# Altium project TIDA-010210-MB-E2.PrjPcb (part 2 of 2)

## Sheet Voltage Sensing-Pg4.SchDoc
size 431 x 279 mm; Date: Not shown in title block; ApprovedBy: Not shown in title block; CheckedBy: Not shown in title block; Author: Not shown in title block; CompanyName: Not shown in title block; DrawnBy: Avinash; Engineer: Not shown in title block; Organization: Not shown in title block; Address1: Not shown in title block; Address2: Not shown in title block; Address3: Not shown in title block; Address4: Not shown in title block; DocumentNumber: 1; Revision: Use project parameter SCH_Rev; SheetNumber: 4; SheetTotal: 7; PageSetup: Record=PageOptions¦CenterHorizontal=True¦CenterVertical=True¦PrintScale=1.00¦XCorrection=1.00¦YCorrection=1.00¦PrintKind=0¦BorderSize=5000000¦LeftOffset=0¦BottomOffset=0¦Orientation=2¦PaperLength=1000¦PaperWidth=1000¦Scale=100¦PaperSource=15¦PrintQuality=600¦MediaType=1¦DitherType=10¦PaperKind=Letter¦PrintScaleMode=1
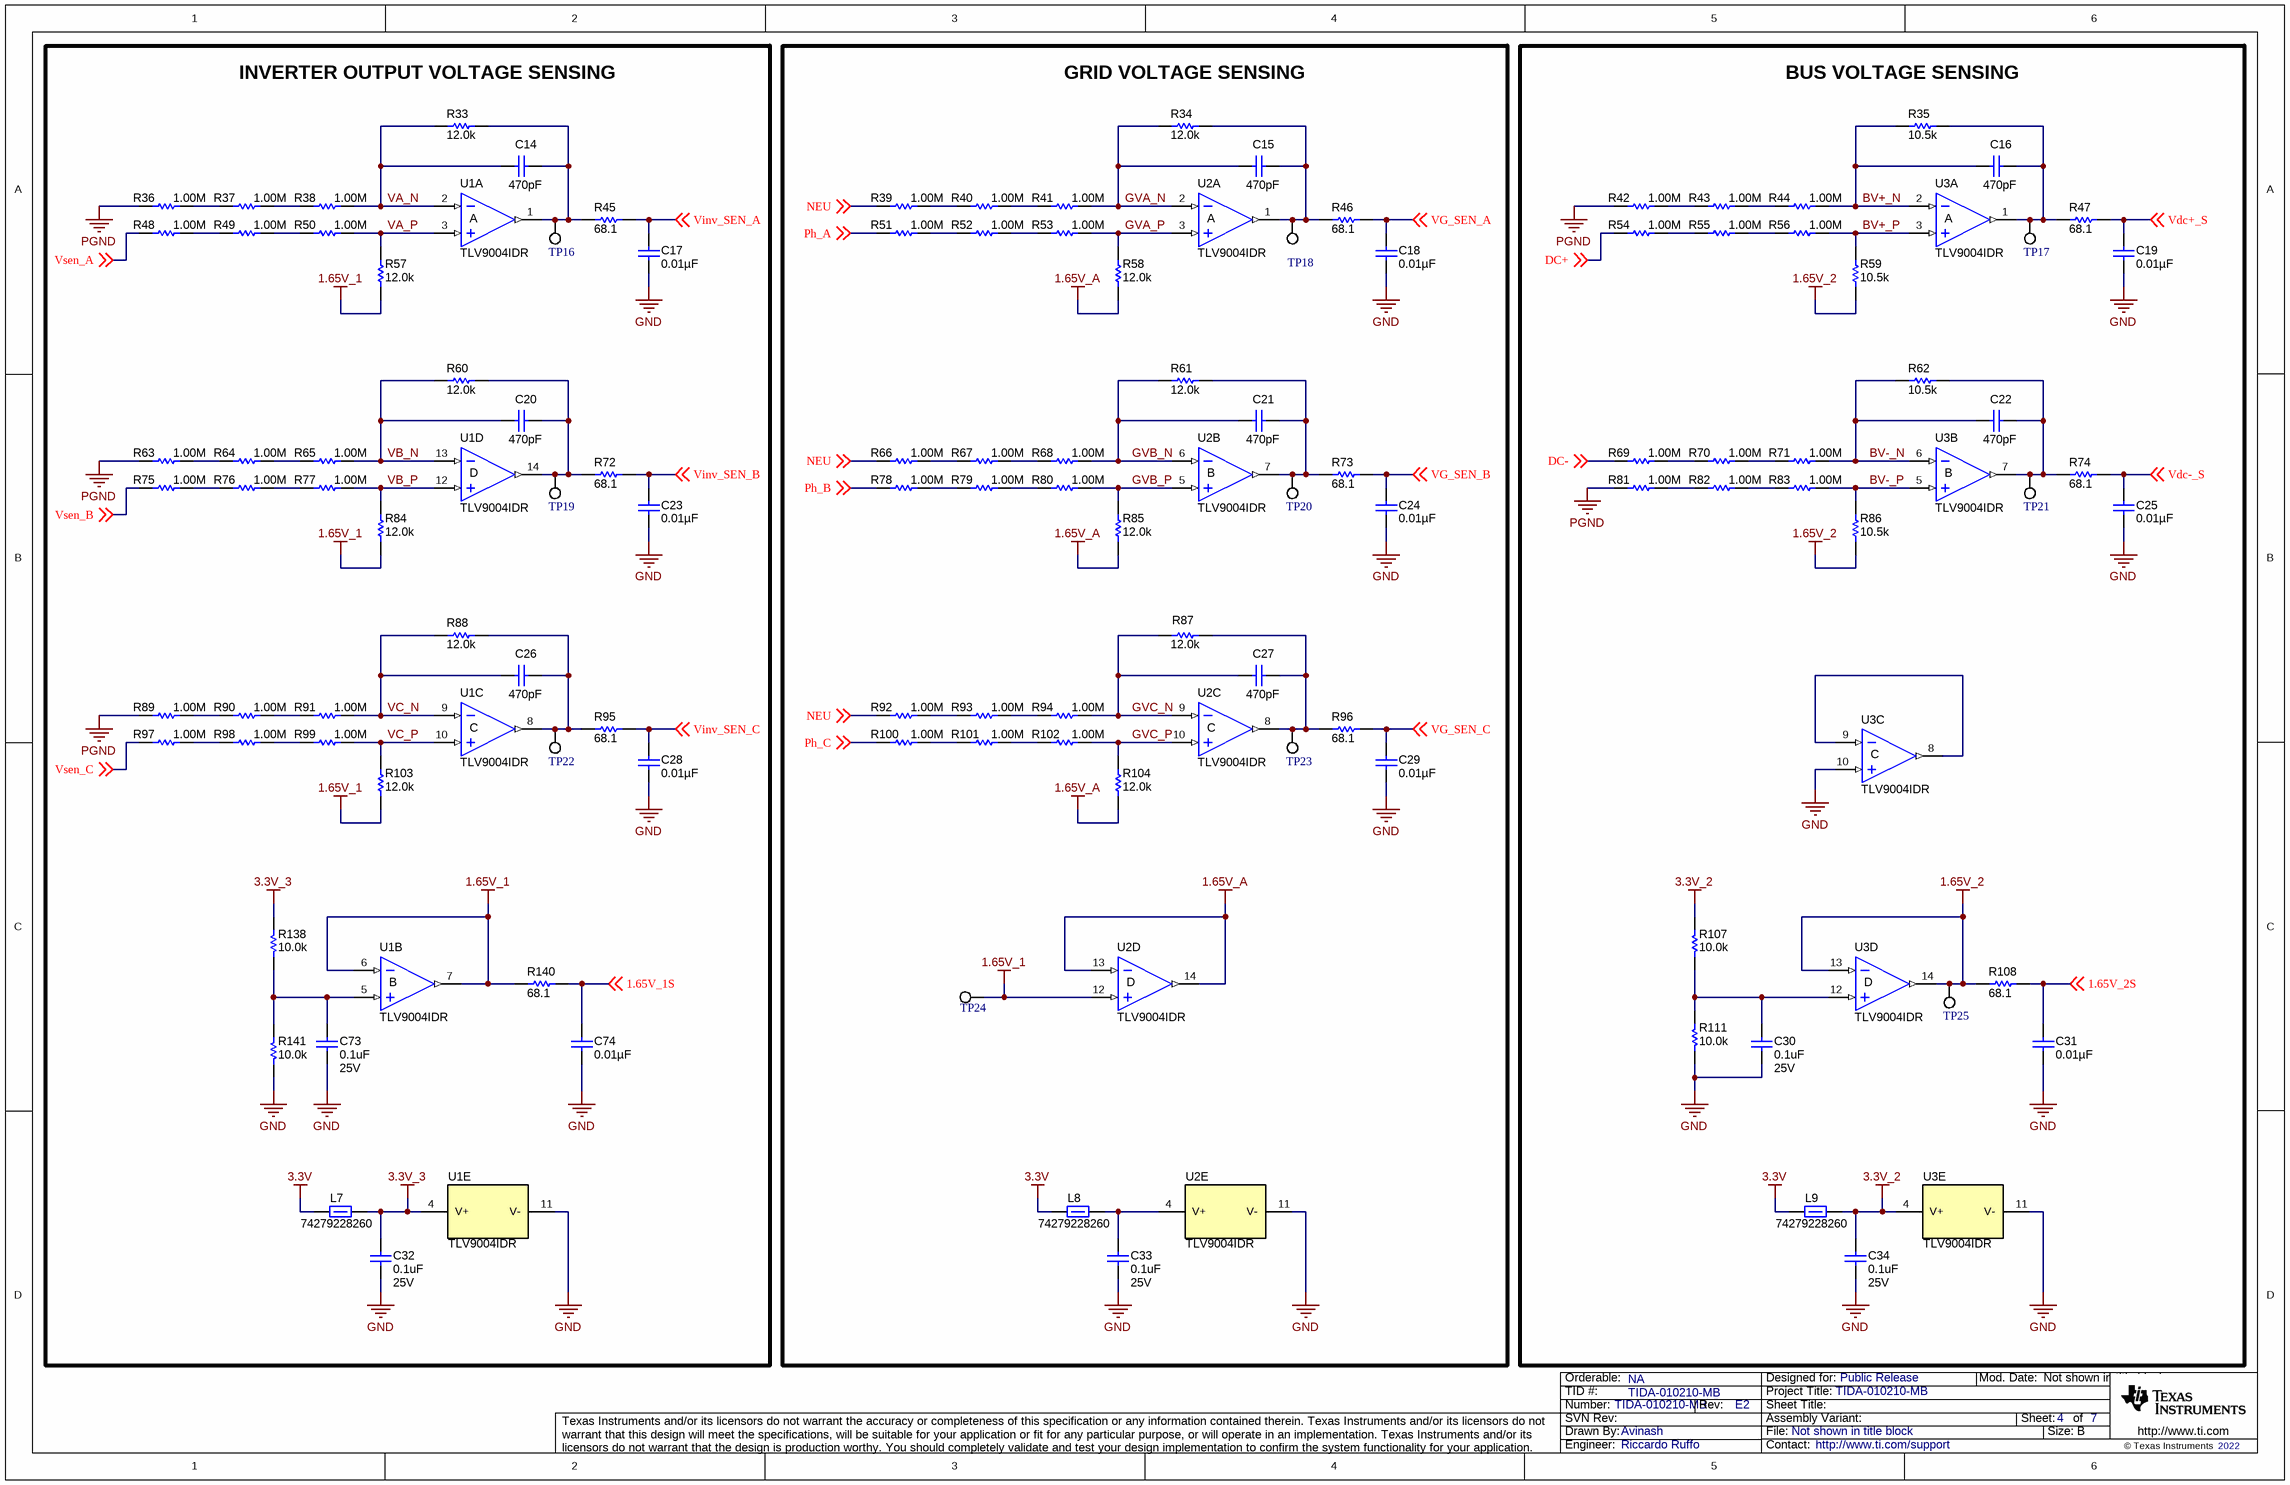
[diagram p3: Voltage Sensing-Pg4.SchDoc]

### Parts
C14  ValueDisplayed: 470pF  [0603]  (hidden comment: 06035A471JAT2A)
C15  ValueDisplayed: 470pF  [0603]  (hidden comment: 06035A471JAT2A)
C16  ValueDisplayed: 470pF  [0603]  (hidden comment: 06035A471JAT2A)
C17  ValueDisplayed: 0.01µF  [0603]  (hidden comment: C0603X103K5RACTU)
C18  ValueDisplayed: 0.01µF  [0603]  (hidden comment: C0603X103K5RACTU)
C19  ValueDisplayed: 0.01µF  [0603]  (hidden comment: C0603X103K5RACTU)
C20  ValueDisplayed: 470pF  [0603]  (hidden comment: 06035A471JAT2A)
C21  ValueDisplayed: 470pF  [0603]  (hidden comment: 06035A471JAT2A)
C22  ValueDisplayed: 470pF  [0603]  (hidden comment: 06035A471JAT2A)
C23  ValueDisplayed: 0.01µF  [0603]  (hidden comment: C0603X103K5RACTU)
C24  ValueDisplayed: 0.01µF  [0603]  (hidden comment: C0603X103K5RACTU)
C25  ValueDisplayed: 0.01µF  [0603]  (hidden comment: C0603X103K5RACTU)
C26  ValueDisplayed: 470pF  [0603]  (hidden comment: 06035A471JAT2A)
C27  ValueDisplayed: 470pF  [0603]  (hidden comment: 06035A471JAT2A)
C28  ValueDisplayed: 0.01µF  [0603]  (hidden comment: C0603X103K5RACTU)
C29  ValueDisplayed: 0.01µF  [0603]  (hidden comment: C0603X103K5RACTU)
C30  ValueDisplayed: 0.1uF  VDC_V: 25V  [0603]  (hidden comment: C0603X104K3RACTU)
C31  ValueDisplayed: 0.01µF  [0603]  (hidden comment: C0603X103K5RACTU)
C32  ValueDisplayed: 0.1uF  VDC_V: 25V  [0603]  (hidden comment: C0603X104K3RACTU)
C33  ValueDisplayed: 0.1uF  VDC_V: 25V  [0603]  (hidden comment: C0603X104K3RACTU)
C34  ValueDisplayed: 0.1uF  VDC_V: 25V  [0603]  (hidden comment: C0603X104K3RACTU)
C73  ValueDisplayed: 0.1uF  VDC_V: 25V  [0603]  (hidden comment: C0603X104K3RACTU)
C74  ValueDisplayed: 0.01µF  [0603]  (hidden comment: C0603X103K5RACTU)
L7  74279228260  [0603]
L8  74279228260  [0603]
L9  74279228260  [0603]
R33  ValueDisplayed: 12.0k  [0603]  (hidden comment: RG1608P-123-B-T5)
R34  ValueDisplayed: 12.0k  [0603]  (hidden comment: RG1608P-123-B-T5)
R35  ValueDisplayed: 10.5k  [0603]  (hidden comment: RT0603BRD0710K5L)
R36  ValueDisplayed: 1.00M  [TNPV1206]  (hidden comment: TNPV12061M00BEEN)
R37  ValueDisplayed: 1.00M  [TNPV1206]  (hidden comment: TNPV12061M00BEEN)
R38  ValueDisplayed: 1.00M  [TNPV1206]  (hidden comment: TNPV12061M00BEEN)
R39  ValueDisplayed: 1.00M  [TNPV1206]  (hidden comment: TNPV12061M00BEEN)
R40  ValueDisplayed: 1.00M  [TNPV1206]  (hidden comment: TNPV12061M00BEEN)
R41  ValueDisplayed: 1.00M  [TNPV1206]  (hidden comment: TNPV12061M00BEEN)
R42  ValueDisplayed: 1.00M  [TNPV1206]  (hidden comment: TNPV12061M00BEEN)
R43  ValueDisplayed: 1.00M  [TNPV1206]  (hidden comment: TNPV12061M00BEEN)
R44  ValueDisplayed: 1.00M  [TNPV1206]  (hidden comment: TNPV12061M00BEEN)
R45  ValueDisplayed: 68.1  [0603]  (hidden comment: CRCW060368R1FKEA)
R46  ValueDisplayed: 68.1  [0603]  (hidden comment: CRCW060368R1FKEA)
R47  ValueDisplayed: 68.1  [0603]  (hidden comment: CRCW060368R1FKEA)
R48  ValueDisplayed: 1.00M  [TNPV1206]  (hidden comment: TNPV12061M00BEEN)
R49  ValueDisplayed: 1.00M  [TNPV1206]  (hidden comment: TNPV12061M00BEEN)
R50  ValueDisplayed: 1.00M  [TNPV1206]  (hidden comment: TNPV12061M00BEEN)
R51  ValueDisplayed: 1.00M  [TNPV1206]  (hidden comment: TNPV12061M00BEEN)
R52  ValueDisplayed: 1.00M  [TNPV1206]  (hidden comment: TNPV12061M00BEEN)
R53  ValueDisplayed: 1.00M  [TNPV1206]  (hidden comment: TNPV12061M00BEEN)
R54  ValueDisplayed: 1.00M  [TNPV1206]  (hidden comment: TNPV12061M00BEEN)
R55  ValueDisplayed: 1.00M  [TNPV1206]  (hidden comment: TNPV12061M00BEEN)
R56  ValueDisplayed: 1.00M  [TNPV1206]  (hidden comment: TNPV12061M00BEEN)
R57  ValueDisplayed: 12.0k  [0603]  (hidden comment: RG1608P-123-B-T5)
R58  ValueDisplayed: 12.0k  [0603]  (hidden comment: RG1608P-123-B-T5)
R59  ValueDisplayed: 10.5k  [0603]  (hidden comment: RT0603BRD0710K5L)
R60  ValueDisplayed: 12.0k  [0603]  (hidden comment: RG1608P-123-B-T5)
R61  ValueDisplayed: 12.0k  [0603]  (hidden comment: RG1608P-123-B-T5)
R62  ValueDisplayed: 10.5k  [0603]  (hidden comment: RT0603BRD0710K5L)
R63  ValueDisplayed: 1.00M  [TNPV1206]  (hidden comment: TNPV12061M00BEEN)
R64  ValueDisplayed: 1.00M  [TNPV1206]  (hidden comment: TNPV12061M00BEEN)
R65  ValueDisplayed: 1.00M  [TNPV1206]  (hidden comment: TNPV12061M00BEEN)
R66  ValueDisplayed: 1.00M  [TNPV1206]  (hidden comment: TNPV12061M00BEEN)
R67  ValueDisplayed: 1.00M  [TNPV1206]  (hidden comment: TNPV12061M00BEEN)
R68  ValueDisplayed: 1.00M  [TNPV1206]  (hidden comment: TNPV12061M00BEEN)
R69  ValueDisplayed: 1.00M  [TNPV1206]  (hidden comment: TNPV12061M00BEEN)
R70  ValueDisplayed: 1.00M  [TNPV1206]  (hidden comment: TNPV12061M00BEEN)
R71  ValueDisplayed: 1.00M  [TNPV1206]  (hidden comment: TNPV12061M00BEEN)
R72  ValueDisplayed: 68.1  [0603]  (hidden comment: CRCW060368R1FKEA)
R73  ValueDisplayed: 68.1  [0603]  (hidden comment: CRCW060368R1FKEA)
R74  ValueDisplayed: 68.1  [0603]  (hidden comment: CRCW060368R1FKEA)
R75  ValueDisplayed: 1.00M  [TNPV1206]  (hidden comment: TNPV12061M00BEEN)
R76  ValueDisplayed: 1.00M  [TNPV1206]  (hidden comment: TNPV12061M00BEEN)
R77  ValueDisplayed: 1.00M  [TNPV1206]  (hidden comment: TNPV12061M00BEEN)
R78  ValueDisplayed: 1.00M  [TNPV1206]  (hidden comment: TNPV12061M00BEEN)
R79  ValueDisplayed: 1.00M  [TNPV1206]  (hidden comment: TNPV12061M00BEEN)
R80  ValueDisplayed: 1.00M  [TNPV1206]  (hidden comment: TNPV12061M00BEEN)
R81  ValueDisplayed: 1.00M  [TNPV1206]  (hidden comment: TNPV12061M00BEEN)
R82  ValueDisplayed: 1.00M  [TNPV1206]  (hidden comment: TNPV12061M00BEEN)
R83  ValueDisplayed: 1.00M  [TNPV1206]  (hidden comment: TNPV12061M00BEEN)
R84  ValueDisplayed: 12.0k  [0603]  (hidden comment: RG1608P-123-B-T5)
R85  ValueDisplayed: 12.0k  [0603]  (hidden comment: RG1608P-123-B-T5)
R86  ValueDisplayed: 10.5k  [0603]  (hidden comment: RT0603BRD0710K5L)
R87  ValueDisplayed: 12.0k  [0603]  (hidden comment: RG1608P-123-B-T5)
R88  ValueDisplayed: 12.0k  [0603]  (hidden comment: RG1608P-123-B-T5)
R89  ValueDisplayed: 1.00M  [TNPV1206]  (hidden comment: TNPV12061M00BEEN)
R90  ValueDisplayed: 1.00M  [TNPV1206]  (hidden comment: TNPV12061M00BEEN)
R91  ValueDisplayed: 1.00M  [TNPV1206]  (hidden comment: TNPV12061M00BEEN)
R92  ValueDisplayed: 1.00M  [TNPV1206]  (hidden comment: TNPV12061M00BEEN)
R93  ValueDisplayed: 1.00M  [TNPV1206]  (hidden comment: TNPV12061M00BEEN)
R94  ValueDisplayed: 1.00M  [TNPV1206]  (hidden comment: TNPV12061M00BEEN)
R95  ValueDisplayed: 68.1  [0603]  (hidden comment: CRCW060368R1FKEA)
R96  ValueDisplayed: 68.1  [0603]  (hidden comment: CRCW060368R1FKEA)
R97  ValueDisplayed: 1.00M  [TNPV1206]  (hidden comment: TNPV12061M00BEEN)
R98  ValueDisplayed: 1.00M  [TNPV1206]  (hidden comment: TNPV12061M00BEEN)
R99  ValueDisplayed: 1.00M  [TNPV1206]  (hidden comment: TNPV12061M00BEEN)
R100  ValueDisplayed: 1.00M  [TNPV1206]  (hidden comment: TNPV12061M00BEEN)
R101  ValueDisplayed: 1.00M  [TNPV1206]  (hidden comment: TNPV12061M00BEEN)
R102  ValueDisplayed: 1.00M  [TNPV1206]  (hidden comment: TNPV12061M00BEEN)
R103  ValueDisplayed: 12.0k  [0603]  (hidden comment: RG1608P-123-B-T5)
R104  ValueDisplayed: 12.0k  [0603]  (hidden comment: RG1608P-123-B-T5)
R107  ValueDisplayed: 10.0k  [0603]  (hidden comment: RG1608P-103-B-T5)
R108  ValueDisplayed: 68.1  [0603]  (hidden comment: CRCW060368R1FKEA)
R111  ValueDisplayed: 10.0k  [0603]  (hidden comment: RG1608P-103-B-T5)
R138  ValueDisplayed: 10.0k  [0603]  (hidden comment: RG1608P-103-B-T5)
R140  ValueDisplayed: 68.1  [0603]  (hidden comment: CRCW060368R1FKEA)
R141  ValueDisplayed: 10.0k  [0603]  (hidden comment: RG1608P-103-B-T5)
TP16  5015  [Testpoint_Keystone_Miniature]  (value not drawn)
TP17  5015  [Testpoint_Keystone_Miniature]  (value not drawn)
TP18  5015  [Testpoint_Keystone_Miniature]  (value not drawn)
TP19  5015  [Testpoint_Keystone_Miniature]  (value not drawn)
TP20  5015  [Testpoint_Keystone_Miniature]  (value not drawn)
TP21  5015  [Testpoint_Keystone_Miniature]  (value not drawn)
TP22  5015  [Testpoint_Keystone_Miniature]  (value not drawn)
TP23  5015  [Testpoint_Keystone_Miniature]  (value not drawn)
TP24  5015  [Testpoint_Keystone_Miniature]  (value not drawn)
TP25  5015  [Testpoint_Keystone_Miniature]  (value not drawn)
U1  TLV9004IDR  [D0014A_N]  (parts A,B,C,D,E of 5)
U2  TLV9004IDR  [D0014A_N]  (parts A,B,C,D,E of 5)
U3  TLV9004IDR  [D0014A_N]  (parts A,B,C,D,E of 5)

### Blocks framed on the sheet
INVERTER OUTPUT VOLTAGE SENSING: C14 C17 C20 C23 C26 C28 C32 C73 C74 L7 R33 R36-R38 R45 R48-R50 R57 R60 R63-R65 R72 R75-R77 R84 R88-R91 R95 R97-R99 R103 R138 R140 R141 TP16 TP19 TP22 U1
GRID VOLTAGE SENSING: C15 C18 C21 C24 C27 C29 C33 L8 R34 R39-R41 R46 R51-R53 R58 R61 R66-R68 R73 R78-R80 R85 R87 R92-R94 R96 R100-R102 R104 TP18 TP20 TP23 TP24 U2
BUS VOLTAGE SENSING: C16 C19 C22 C25 C30 C31 C34 L9 R35 R42-R44 R47 R54-R56 R59 R62 R69-R71 R74 R81-R83 R86 R107 R108 R111 TP17 TP21 TP25 U3

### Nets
1.65V_1: R57.1 R84.1 R103.1 R140.1 TP24.1 U1.6(IN-) U1.7(OUT) U2.12(IN+)
1.65V_2: R59.1 R86.1 R108.1 TP25.1 U3.13(IN-) U3.14(OUT)
1.65V_A: R58.1 R85.1 R104.1 U2.13(IN-) U2.14(OUT)
3.3V: L7.1 L8.1 L9.1
3.3V_2: C34.2 L9.2 R107.1 U3.4(V+)
3.3V_3: C32.2 L7.2 R138.1 U1.4(V+)
GND: C17.2 C18.2 C19.2 C23.2 C24.2 C25.2 C28.2 C29.2 C30.1 C31.2 C32.1 C33.1 C34.1 C73.1 C74.2 R111.2 R141.2 U1.11(V-) U2.11(V-) U3.10(IN+) U3.11(V-)
PGND: R36.1 R39.1 R42.1 R63.1 R66.1 R81.1 R89.1 R92.1 ; off-sheet NEU  [also labelled NEU]
1.65V_1S: C74.1 R140.2 ; off-sheet 1.65V_1S
1.65V_2S: C31.1 R108.2 ; off-sheet 1.65V_2S
BV+_N: C16.2 R35.1 R44.2 U3.2(IN-)
BV+_P: R56.2 R59.2 U3.3(IN+)
BV-_N: C22.2 R62.1 R71.2 U3.6(IN-)
BV-_P: R83.2 R86.2 U3.5(IN+)
DC+: R54.1 ; off-sheet DC+
DC-: R69.1 ; off-sheet DC-
GVA_N: C15.2 R34.1 R41.2 U2.2(IN-)
GVA_P: R53.2 R58.2 U2.3(IN+)
GVB_N: C21.2 R61.1 R68.2 U2.6(IN-)
GVB_P: R80.2 R85.2 U2.5(IN+)
GVC_N: C27.2 R87.1 R94.2 U2.9(IN-)
GVC_P: R102.2 R104.2 U2.10(IN+)
Ph_A: R51.1 ; off-sheet Ph_A
Ph_B: R78.1 ; off-sheet Ph_B
Ph_C: R100.1 ; off-sheet Ph_C
VA_N: C14.2 R33.1 R38.2 U1.2(IN-)
VA_P: R50.2 R57.2 U1.3(IN+)
VB_N: C20.2 R60.1 R65.2 U1.13(IN-)
VB_P: R77.2 R84.2 U1.12(IN+)
VC_N: C26.2 R88.1 R91.2 U1.9(IN-)
VC_P: R99.2 R103.2 U1.10(IN+)
Vdc+_S: C19.1 R47.2 ; off-sheet Vdc+_S
Vdc-_S: C25.1 R74.2 ; off-sheet Vdc-_S
VG_SEN_A: C18.1 R46.2 ; off-sheet VG_SEN_A
VG_SEN_B: C24.1 R73.2 ; off-sheet VG_SEN_B
VG_SEN_C: C29.1 R96.2 ; off-sheet VG_SEN_C
Vinv_SEN_A: C17.1 R45.2 ; off-sheet Vinv_SEN_A
Vinv_SEN_B: C23.1 R72.2 ; off-sheet Vinv_SEN_B
Vinv_SEN_C: C28.1 R95.2 ; off-sheet Vinv_SEN_C
Vsen_A: R48.1 ; off-sheet Vsen_A
Vsen_B: R75.1 ; off-sheet Vsen_B
Vsen_C: R97.1 ; off-sheet Vsen_C
NetC14_1: C14.1 R33.2 R45.1 TP16.1 U1.1(OUT)
NetC15_1: C15.1 R34.2 R46.1 TP18.1 U2.1(OUT)
NetC16_1: C16.1 R35.2 R47.1 TP17.1 U3.1(OUT)
NetC20_1: C20.1 R60.2 R72.1 TP19.1 U1.14(OUT)
NetC21_1: C21.1 R61.2 R73.1 TP20.1 U2.7(OUT)
NetC22_1: C22.1 R62.2 R74.1 TP21.1 U3.7(OUT)
NetC26_1: C26.1 R88.2 R95.1 TP22.1 U1.8(OUT)
NetC27_1: C27.1 R87.2 R96.1 TP23.1 U2.8(OUT)
NetC30_2: C30.2 R107.2 R111.1 U3.12(IN+)
NetC33_2: C33.2 L8.2 U2.4(V+)
NetC73_2: C73.2 R138.2 R141.1 U1.5(IN+)
NetR36_2: R36.2 R37.1
NetR37_2: R37.2 R38.1
NetR39_2: R39.2 R40.1
NetR40_2: R40.2 R41.1
NetR42_2: R42.2 R43.1
NetR43_2: R43.2 R44.1
NetR48_2: R48.2 R49.1
NetR49_2: R49.2 R50.1
NetR51_2: R51.2 R52.1
NetR52_2: R52.2 R53.1
NetR54_2: R54.2 R55.1
NetR55_2: R55.2 R56.1
NetR63_2: R63.2 R64.1
NetR64_2: R64.2 R65.1
NetR66_2: R66.2 R67.1
NetR67_2: R67.2 R68.1
NetR69_2: R69.2 R70.1
NetR70_2: R70.2 R71.1
NetR75_2: R75.2 R76.1
NetR76_2: R76.2 R77.1
NetR78_2: R78.2 R79.1
NetR79_2: R79.2 R80.1
NetR81_2: R81.2 R82.1
NetR82_2: R82.2 R83.1
NetR89_2: R89.2 R90.1
NetR90_2: R90.2 R91.1
NetR92_2: R92.2 R93.1
NetR93_2: R93.2 R94.1
NetR97_2: R97.2 R98.1
NetR98_2: R98.2 R99.1
NetR100_2: R100.2 R101.1
NetR101_2: R101.2 R102.1
NetU3_8: U3.8(OUT) U3.9(IN-)

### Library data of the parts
C14-C16 C20-C22 C26 C27 = CMP-0006790-4: CAP, CERM, 470 pF, 50 V, +/- 5%, C0G/NP0, 0603; Manufacturer: AVX; TaMin_C: -55°C; ESR_ohm: 0.063; Polarized: N; SizeAreaWB_mm2: 4.68; Value1: 0.063 ohm; U/M: EA; Value: 470pF; TaMax_C: 125°C; SizeZ_mm: 1; SizeX_mm: 1.6; SizeY_mm: 0.8; Value2: 50V; SizeArea_mm2: 1.28; AEC Category: Q200
C17-C19 C23-C25 C28 C29 C31 C74 = C0603X103K5RACTU: CAP, CERM, 0.01uF, 50V, +/-10%, X7R, 0603; Manufacturer: Kemet; Polarized: N; CompType: Capacitor; U/M: EA; Cap_F: 0.00000001; Tolerance_%: 10; Value1: Unknown; VDC_V: 50; TaMin_C: -55; TaMax_C: 125
C30 C32-C34 C73 = CMP-0006979-5: CAP, CERM, 0.1 uF, 25 V, +/- 10%, X7R, 0603; Manufacturer: Kemet; Polarized: N; Value: 0.1uF; U/M: EA; Cap_F: 100nF; Value1: Unknown; TaMin_C: -55°C; TaMax_C: 125°C; SizeArea_mm2: 1.28; SizeAreaWB_mm2: 4.68; SizeX_mm: 1.6; SizeY_mm: 0.8; SizeZ_mm: 1; AEC Category: Q200
L7-L9 = CMP-0003155-2: Ferrite Bead, 26 ohm @ 100 MHz, 6.5 A, 0603; Manufacturer: Wurth Elektronik; Ztyp@1GHz_Ohm: 35.506; ZTyp@100MHz_Ohm: 26; SizeAreaWB_mm2: 4.68; DCR_ohm: 5m; Value1: 0.005 ohm; Value: 26 ohm; Imax_A: 6.5A; SizeZ_mm: 1; SizeX_mm: 1.6; SizeY_mm: 0.8; SizeArea_mm2: 1.28
R33 R34 R57 R58 R60 R61 R84 R85 R87 R88 R103 R104 = CMP-0023423-3: RES, 12.0 k, 0.1%, 0.1 W, 0603; Manufacturer: Susumu Co Ltd; Power_W: 100mW; TempCo: 25 ppm/C; Value_Code: 12k0; U/M: EA; Value: 12.0k; EIA_Code: E192; Res_ohm: 12k; SizeX_mm: 1.6; SizeY_mm: 0.8; SizeZ_mm: 1; Value2: 0.1W; SizeArea_mm2: 1.28; VDC_V: 75V; AEC Category: Q200
R35 R59 R62 R86 = CMP-0023649-3: RES, 10.5 k, 0.1%, 0.1 W, 0603; Manufacturer: Yageo America; Power_W: 100mW; TempCo: 25 ppm/C; Value_Code: 10k5; U/M: EA; Value: 10.5k; EIA_Code: E192; SizeX_mm: 1.6; SizeY_mm: 0.8; SizeZ_mm: 1; Value2: 0.1W; SizeArea_mm2: 1.28; VDC_V: 75V; AEC Category: Q200
R36-R44 R48-R56 R63-R71 R75-R83 R89-R94 R97-R102 = CMP-0018805-2: RES, 1.00 M, 0.1%, 1 W, 1206; Manufacturer: Vishay Draloric; Power_W: 1W; TempCo: 25 ppm/C; Value_Code: 1M00; U/M: EA; Value: 1.00Meg; EIA_Code: E192; Res_ohm: 1M; SizeX_mm: 3.2; SizeY_mm: 1.6; SizeZ_mm: 0.65; SizeArea_mm2: 5.12; AEC Qualified: N; VDC_V: 700V; AEC Category: Q200
R45-R47 R72-R74 R95 R96 R108 R140 = CMP-0022553-4: RES, 68.1, 1%, 0.1 W, AEC-Q200 Grade 0, 0603; Manufacturer: Vishay-Dale; Value: 68.1; Value_Code: 68R1; Power_W: 100mW; Value2: 0.1W; VDC_V: 75V; TempCo: 100 ppm/C; SizeArea_mm2: 1.28; SizeX_mm: 1.6; SizeY_mm: 0.8; SizeZ_mm: 1; EIA_Code: E96; AEC Category: Q200; AEC Qualified: Y; AEC Grade: 0
R107 R111 R138 R141 = CMP-0023404-3: RES, 10.0 k, 0.1%, 0.1 W, 0603; Manufacturer: Susumu Co Ltd; Value: 10.0k; Res_ohm: 10k; Value_Code: 10k0; Power_W: 100mW; Value2: 0.1W; VDC_V: 75V; TempCo: 25 ppm/C; SizeArea_mm2: 1.28; SizeX_mm: 1.6; SizeY_mm: 0.8; SizeZ_mm: 1; EIA_Code: E192; U/M: EA; AEC Category: Q200
TP16-TP25 = 5015: Test Point, Miniature, SMT; Manufacturer: Keystone; CompType: Test Point Loop; Green_Lifecycle: Active; Green_REACh: Passed
U1-U3 = CMP-0860066-1: 4-Channel, 1MHz, RRIO, 1.8V to 5.5V Operational Amplifier for Cost-Optimized Systems, D0014A (SOIC-14); Manufacturer: Texas Instruments; SizeY_mm: 8.65; AEC Qualified: N; Rating: Catalog; SizeAreaWB_mm2: 85.2; SizeZ_mm: 1.75; AEC Category: Q200; SizeArea_mm2: 51.9; CompType: IC; SizeX_mm: 6

## Sheet Current Sensing-Pg5.SchDoc: Inductor Current Sensing Interface Circuit
size 431 x 279 mm; Date: Not shown in title block; ApprovedBy: Not shown in title block; CheckedBy: Not shown in title block; Author: Not shown in title block; CompanyName: Not shown in title block; DrawnBy: Avinash; Engineer: Not shown in title block; Organization: Not shown in title block; Address1: Not shown in title block; Address2: Not shown in title block; Address3: Not shown in title block; Address4: Not shown in title block; DocumentNumber: 1; Revision: Use project parameter SCH_Rev; SheetNumber: 5; SheetTotal: 7; PageSetup: Record=PageOptions¦CenterHorizontal=True¦CenterVertical=True¦PrintScale=1.00¦XCorrection=1.00¦YCorrection=1.00¦PrintKind=0¦BorderSize=5000000¦LeftOffset=0¦BottomOffset=0¦Orientation=2¦PaperLength=1000¦PaperWidth=1000¦Scale=100¦PaperSource=15¦PrintQuality=600¦MediaType=1¦DitherType=10¦PaperKind=Letter¦PrintScaleMode=1
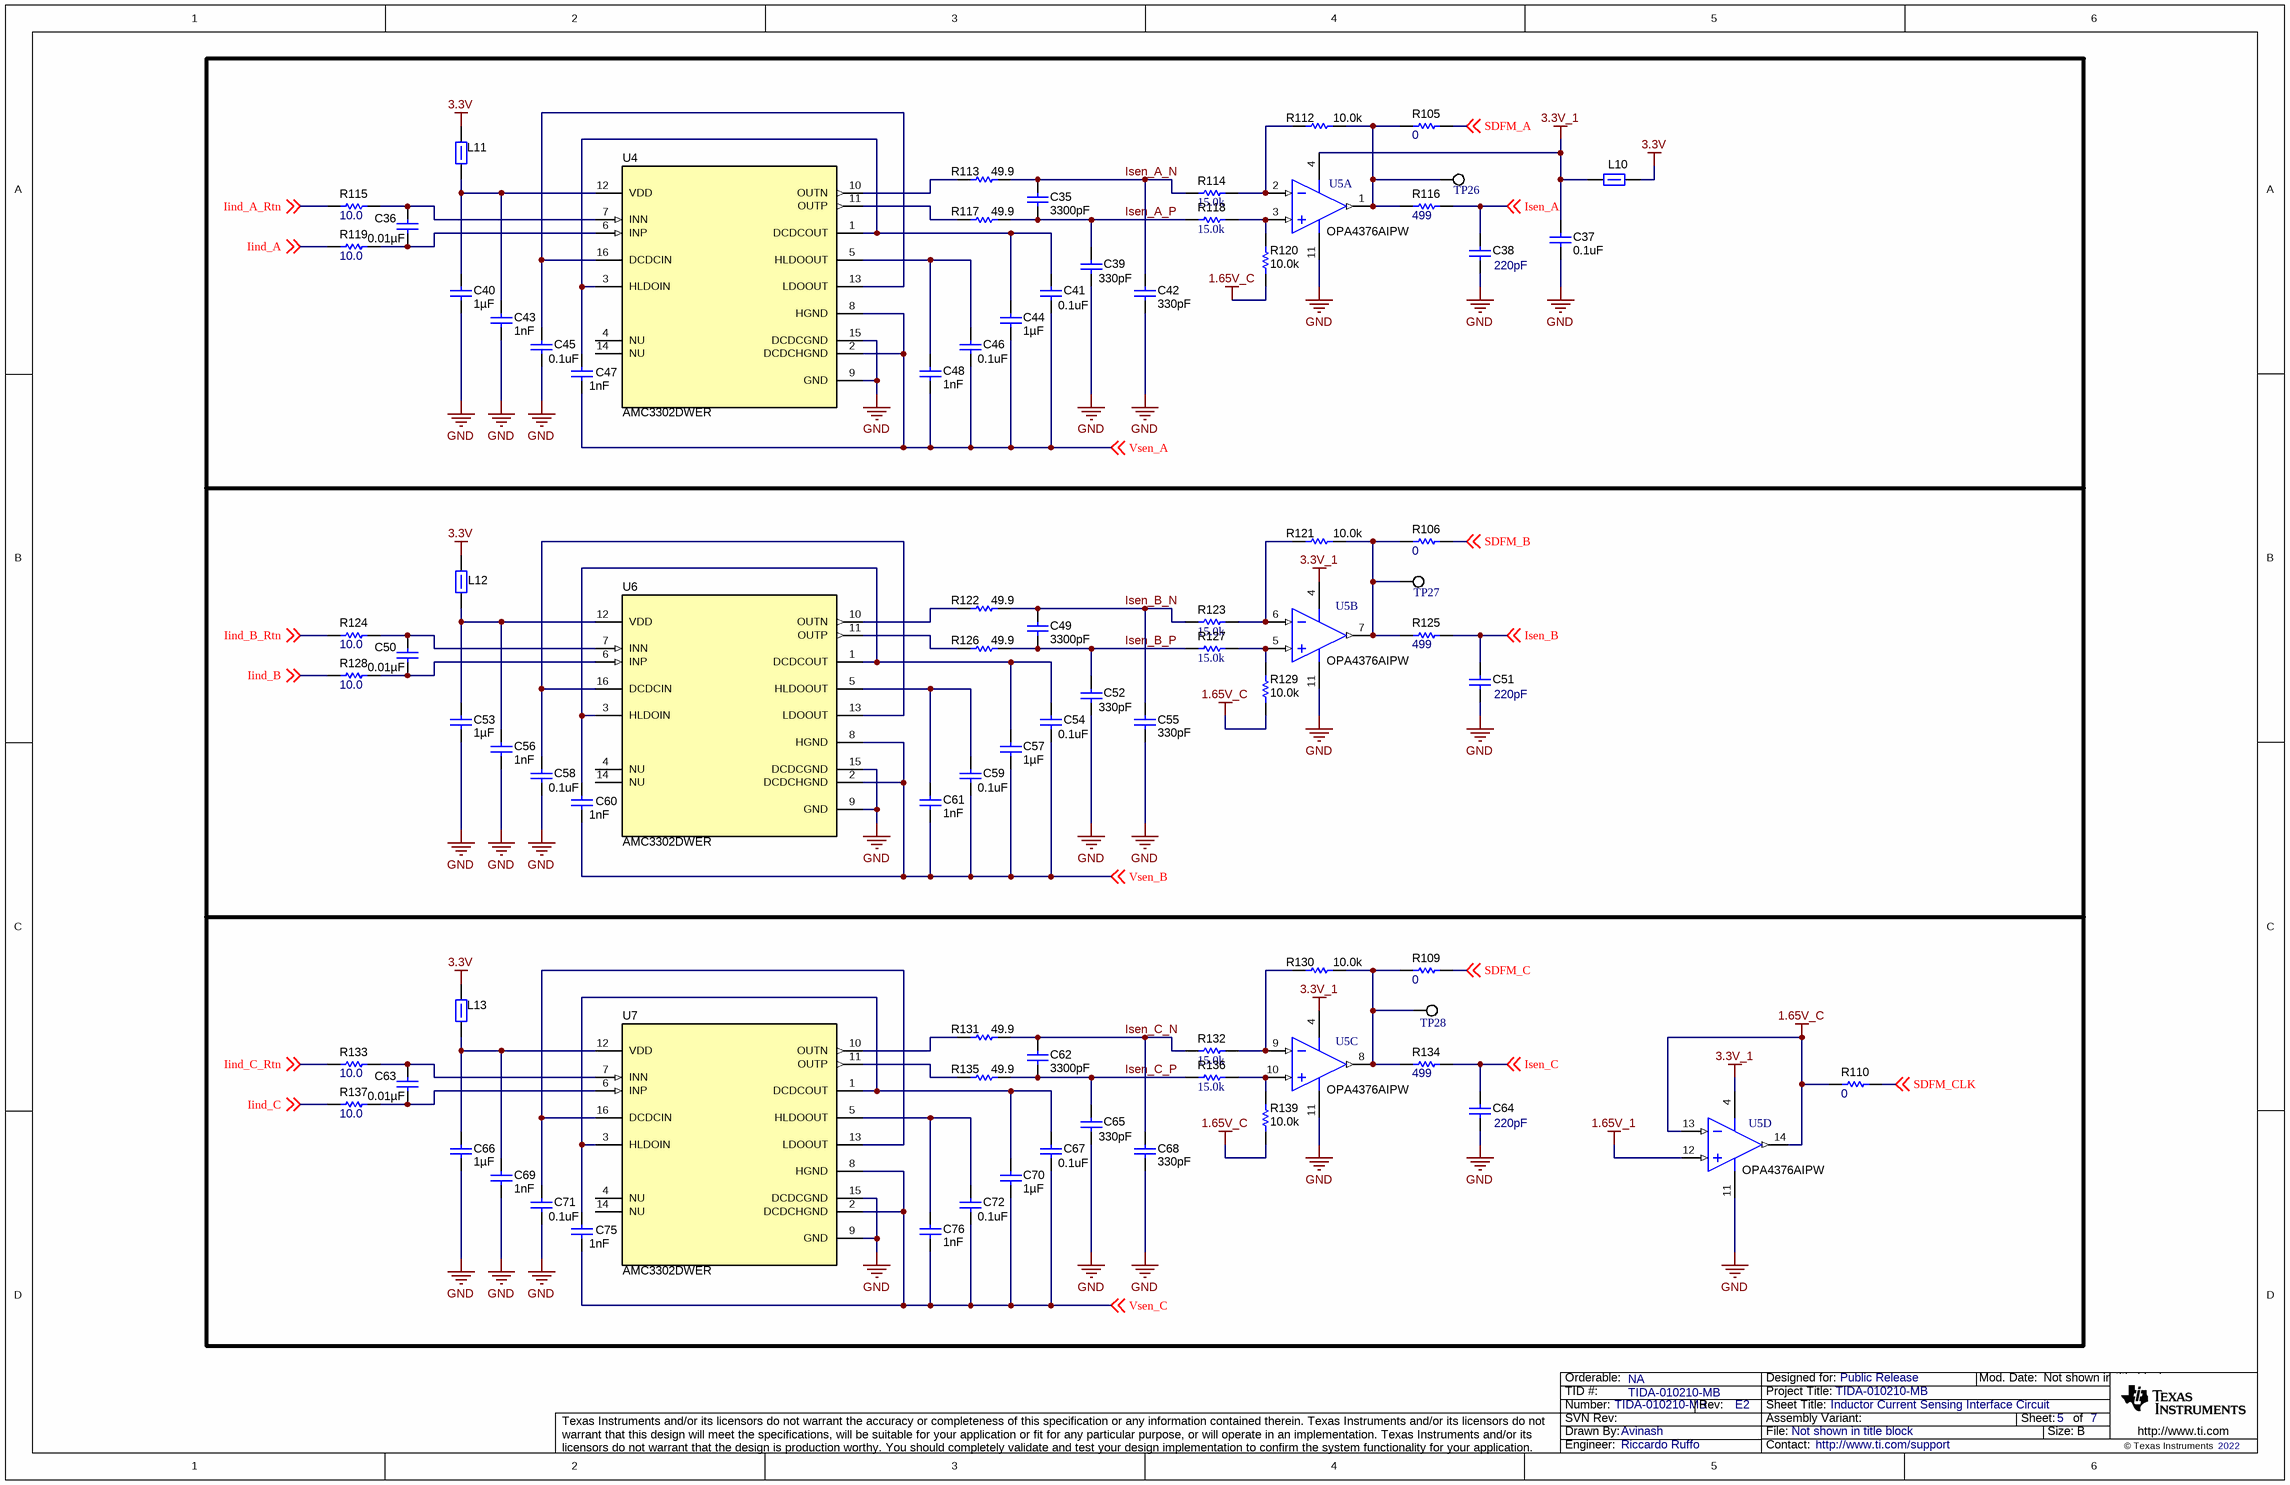
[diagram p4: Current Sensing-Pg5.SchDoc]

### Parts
C35  ValueDisplayed: 3300pF  [0603]  (hidden comment: GRM1885C1H332JA01D)
C36  ValueDisplayed: 0.01µF  [0603]  (hidden comment: C0603X103K5RACTU)
C37  ValueDisplayed: 0.1uF  [0603]  (hidden comment: C0603X104K3RACTU)
C38  ValueDisplayed: 220pF  [0603]  (hidden comment: GRM1885C1H221JA01D)
C39  ValueDisplayed: 330pF  [0603]  (hidden comment: 06035A331JAT2A)
C40  Cap_F: 1µF  [0603]  (hidden comment: GRJ188R71E105KE11D)
C41  ValueDisplayed: 0.1uF  [0603]  (hidden comment: C0603X104K3RACTU)
C42  ValueDisplayed: 330pF  [0603]  (hidden comment: 06035A331JAT2A)
C43  Cap_F: 1nF  [0603]  (hidden comment: GRM188R71H102JA01D)
C44  Cap_F: 1µF  [0603]  (hidden comment: GRJ188R71E105KE11D)
C45  ValueDisplayed: 0.1uF  [0603]  (hidden comment: C0603X104K3RACTU)
C46  ValueDisplayed: 0.1uF  [0603]  (hidden comment: C0603X104K3RACTU)
C47  Cap_F: 1nF  [0603]  (hidden comment: GRM188R71H102JA01D)
C48  Cap_F: 1nF  [0603]  (hidden comment: GRM188R71H102JA01D)
C49  ValueDisplayed: 3300pF  [0603]  (hidden comment: GRM1885C1H332JA01D)
C50  ValueDisplayed: 0.01µF  [0603]  (hidden comment: C0603X103K5RACTU)
C51  ValueDisplayed: 220pF  [0603]  (hidden comment: GRM1885C1H221JA01D)
C52  ValueDisplayed: 330pF  [0603]  (hidden comment: 06035A331JAT2A)
C53  Cap_F: 1µF  [0603]  (hidden comment: GRJ188R71E105KE11D)
C54  ValueDisplayed: 0.1uF  [0603]  (hidden comment: C0603X104K3RACTU)
C55  ValueDisplayed: 330pF  [0603]  (hidden comment: 06035A331JAT2A)
C56  Cap_F: 1nF  [0603]  (hidden comment: GRM188R71H102JA01D)
C57  Cap_F: 1µF  [0603]  (hidden comment: GRJ188R71E105KE11D)
C58  ValueDisplayed: 0.1uF  [0603]  (hidden comment: C0603X104K3RACTU)
C59  ValueDisplayed: 0.1uF  [0603]  (hidden comment: C0603X104K3RACTU)
C60  Cap_F: 1nF  [0603]  (hidden comment: GRM188R71H102JA01D)
C61  Cap_F: 1nF  [0603]  (hidden comment: GRM188R71H102JA01D)
C62  ValueDisplayed: 3300pF  [0603]  (hidden comment: GRM1885C1H332JA01D)
C63  ValueDisplayed: 0.01µF  [0603]  (hidden comment: C0603X103K5RACTU)
C64  ValueDisplayed: 220pF  [0603]  (hidden comment: GRM1885C1H221JA01D)
C65  ValueDisplayed: 330pF  [0603]  (hidden comment: 06035A331JAT2A)
C66  Cap_F: 1µF  [0603]  (hidden comment: GRJ188R71E105KE11D)
C67  ValueDisplayed: 0.1uF  [0603]  (hidden comment: C0603X104K3RACTU)
C68  ValueDisplayed: 330pF  [0603]  (hidden comment: 06035A331JAT2A)
C69  Cap_F: 1nF  [0603]  (hidden comment: GRM188R71H102JA01D)
C70  Cap_F: 1µF  [0603]  (hidden comment: GRJ188R71E105KE11D)
C71  ValueDisplayed: 0.1uF  [0603]  (hidden comment: C0603X104K3RACTU)
C72  ValueDisplayed: 0.1uF  [0603]  (hidden comment: C0603X104K3RACTU)
C75  Cap_F: 1nF  [0603]  (hidden comment: GRM188R71H102JA01D)
C76  Cap_F: 1nF  [0603]  (hidden comment: GRM188R71H102JA01D)
L10  74279228260  [0603]  (value not drawn)
L11  74279228260  [0603]  (value not drawn)
L12  74279228260  [0603]  (value not drawn)
L13  74279228260  [0603]  (value not drawn)
R105  ValueDisplayed: 0  [0603]  (hidden comment: RCS06030000Z0EA)
R106  ValueDisplayed: 0  [0603]  (hidden comment: RCS06030000Z0EA)
R109  ValueDisplayed: 0  [0603]  (hidden comment: RCS06030000Z0EA)
R110  ValueDisplayed: 0  [0603]  (hidden comment: RCS06030000Z0EA)
R112  ValueDisplayed: 10.0k  [0603]  (hidden comment: PHT0603Y1002BGT200)
R113  ValueDisplayed: 49.9  [0603]  (hidden comment: RC0603FR-0749R9L)
R114  ValueDisplayed: 15.0k  [0603]  (hidden comment: RT0603BRD0715KL)
R115  ValueDisplayed: 10.0  [0603]  (hidden comment: CRCW060310R0FKEA)
R116  ValueDisplayed: 499  [0603]  (hidden comment: CRCW0603499RFKEAC)
R117  ValueDisplayed: 49.9  [0603]  (hidden comment: RC0603FR-0749R9L)
R118  ValueDisplayed: 15.0k  [0603]  (hidden comment: RT0603BRD0715KL)
R119  ValueDisplayed: 10.0  [0603]  (hidden comment: CRCW060310R0FKEA)
R120  ValueDisplayed: 10.0k  [0603]  (hidden comment: PHT0603Y1002BGT200)
R121  ValueDisplayed: 10.0k  [0603]  (hidden comment: PHT0603Y1002BGT200)
R122  ValueDisplayed: 49.9  [0603]  (hidden comment: RC0603FR-0749R9L)
R123  ValueDisplayed: 15.0k  [0603]  (hidden comment: RT0603BRD0715KL)
R124  ValueDisplayed: 10.0  [0603]  (hidden comment: CRCW060310R0FKEA)
R125  ValueDisplayed: 499  [0603]  (hidden comment: CRCW0603499RFKEAC)
R126  ValueDisplayed: 49.9  [0603]  (hidden comment: RC0603FR-0749R9L)
R127  ValueDisplayed: 15.0k  [0603]  (hidden comment: RT0603BRD0715KL)
R128  ValueDisplayed: 10.0  [0603]  (hidden comment: CRCW060310R0FKEA)
R129  ValueDisplayed: 10.0k  [0603]  (hidden comment: PHT0603Y1002BGT200)
R130  ValueDisplayed: 10.0k  [0603]  (hidden comment: PHT0603Y1002BGT200)
R131  ValueDisplayed: 49.9  [0603]  (hidden comment: RC0603FR-0749R9L)
R132  ValueDisplayed: 15.0k  [0603]  (hidden comment: RT0603BRD0715KL)
R133  ValueDisplayed: 10.0  [0603]  (hidden comment: CRCW060310R0FKEA)
R134  ValueDisplayed: 499  [0603]  (hidden comment: CRCW0603499RFKEAC)
R135  ValueDisplayed: 49.9  [0603]  (hidden comment: RC0603FR-0749R9L)
R136  ValueDisplayed: 15.0k  [0603]  (hidden comment: RT0603BRD0715KL)
R137  ValueDisplayed: 10.0  [0603]  (hidden comment: CRCW060310R0FKEA)
R139  ValueDisplayed: 10.0k  [0603]  (hidden comment: PHT0603Y1002BGT200)
TP26  5015  [Testpoint_Keystone_Miniature]  (value not drawn)
TP27  5015  [Testpoint_Keystone_Miniature]  (value not drawn)
TP28  5015  [Testpoint_Keystone_Miniature]  (value not drawn)
U4  PartNumber: AMC3302DWER  [DWE0016A]  (hidden comment: AMC3301DWER)
U5  OPA4376AIPW  [PW0014A_N]  (parts A,B,C,D of 4)
U6  PartNumber: AMC3302DWER  [DWE0016A]  (hidden comment: AMC3301DWER)
U7  PartNumber: AMC3302DWER  [DWE0016A]  (hidden comment: AMC3301DWER)

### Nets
1.65V_1: U5.12(IN_D+)
1.65V_C: R110.1 R120.1 R129.1 R139.1 U5.13(IN_D-) U5.14(OUT_D)
3.3V: L10.1 L11.2 L12.2 L13.2
3.3V_1: C37.2 L10.2 U5.4(V+)
GND: C37.1 C38.2 C39.2 C40.2 C42.2 C43.2 C45.1 C51.2 C52.2 C53.2 C55.2 C56.2 C58.1 C64.2 C65.2 C66.2 C68.2 C69.2 C71.1 U4.9(GND) U4.15(DCDCGND) U5.11(V-) U6.9(GND) U6.15(DCDCGND) U7.9(GND) U7.15(DCDCGND)
Iind_A: R119.1 ; off-sheet Iind_A
Iind_A_Rtn: R115.1 ; off-sheet Iind_A_Rtn
Iind_B: R128.1 ; off-sheet Iind_B
Iind_B_Rtn: R124.1 ; off-sheet Iind_B_Rtn
Iind_C: R137.1 ; off-sheet Iind_C
Iind_C_Rtn: R133.1 ; off-sheet Iind_C_Rtn
Isen_A: C38.1 R116.2 ; off-sheet Isen_A
Isen_A_N: C35.1 C42.1 R113.2 R114.1
Isen_A_P: C35.2 C39.1 R117.2 R118.1
Isen_B: C51.1 R125.2 ; off-sheet Isen_B
Isen_B_N: C49.1 C55.1 R122.2 R123.1
Isen_B_P: C49.2 C52.1 R126.2 R127.1
Isen_C: C64.1 R134.2 ; off-sheet Isen_C
Isen_C_N: C62.1 C68.1 R131.2 R132.1
Isen_C_P: C62.2 C65.1 R135.2 R136.1
SDFM_A: R105.2 ; off-sheet SDFM_A
SDFM_B: R106.2 ; off-sheet SDFM_B
SDFM_C: R109.2 ; off-sheet SDFM_C
SDFM_CLK: R110.2 ; off-sheet SDFM_CLK
Vsen_A: C41.1 C44.2 C46.1 C47.2 C48.2 U4.2(DCDCHGND) U4.8(HGND) ; off-sheet Vsen_A
Vsen_B: C54.1 C57.2 C59.1 C60.2 C61.2 U6.2(DCDCHGND) U6.8(HGND) ; off-sheet Vsen_B
Vsen_C: C67.1 C70.2 C72.1 C75.2 C76.2 U7.2(DCDCHGND) U7.8(HGND) ; off-sheet Vsen_C
NetC36_1: C36.1 R115.2 U4.7(INN)
NetC36_2: C36.2 R119.2 U4.6(INP)
NetC40_1: C40.1 C43.1 L11.1 U4.12(VDD)
NetC41_2: C41.2 C44.1 C47.1 U4.1(DCDCOUT) U4.3(HLDOIN)
NetC45_2: C45.2 U4.13(LDOOUT) U4.16(DCDCIN)
NetC46_2: C46.2 C48.1 U4.5(HLDOOUT)
NetC50_1: C50.1 R124.2 U6.7(INN)
NetC50_2: C50.2 R128.2 U6.6(INP)
NetC53_1: C53.1 C56.1 L12.1 U6.12(VDD)
NetC54_2: C54.2 C57.1 C60.1 U6.1(DCDCOUT) U6.3(HLDOIN)
NetC58_2: C58.2 U6.13(LDOOUT) U6.16(DCDCIN)
NetC59_2: C59.2 C61.1 U6.5(HLDOOUT)
NetC63_1: C63.1 R133.2 U7.7(INN)
NetC63_2: C63.2 R137.2 U7.6(INP)
NetC66_1: C66.1 C69.1 L13.1 U7.12(VDD)
NetC67_2: C67.2 C70.1 C75.1 U7.1(DCDCOUT) U7.3(HLDOIN)
NetC71_2: C71.2 U7.13(LDOOUT) U7.16(DCDCIN)
NetC72_2: C72.2 C76.1 U7.5(HLDOOUT)
NetR105_1: R105.1 R112.2 R116.1 TP26.1 U5.1(OUT_A)
NetR106_1: R106.1 R121.2 R125.1 TP27.1 U5.7(OUT_B)
NetR109_1: R109.1 R130.2 R134.1 TP28.1 U5.8(OUT_C)
NetR112_1: R112.1 R114.2 U5.2(IN_A-)
NetR113_1: R113.1 U4.10(OUTN)
NetR117_1: R117.1 U4.11(OUTP)
NetR118_2: R118.2 R120.2 U5.3(IN_A+)
NetR121_1: R121.1 R123.2 U5.6(IN_B-)
NetR122_1: R122.1 U6.10(OUTN)
NetR126_1: R126.1 U6.11(OUTP)
NetR127_2: R127.2 R129.2 U5.5(IN_B+)
NetR130_1: R130.1 R132.2 U5.9(IN_C-)
NetR131_1: R131.1 U7.10(OUTN)
NetR135_1: R135.1 U7.11(OUTP)
NetR136_2: R136.2 R139.2 U5.10(IN_C+)

Not connected (* = marked no-connect by the designer): U4 4(NU) 14(NU); U6 4(NU) 14(NU); U7 4(NU) 14(NU)

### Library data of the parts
C35 C49 C62 = CMP-0007210-4: CAP, CERM, 3300 pF, 50 V, +/- 5%, C0G/NP0, 0603; Manufacturer: MuRata; TaMin_C: -55°C; Polarized: N; SizeAreaWB_mm2: 4.68; Value1: Unknown; U/M: EA; Value: 3300pF; TaMax_C: 125°C; SizeZ_mm: 1; SizeX_mm: 1.6; SizeY_mm: 0.8; Value2: 50V; SizeArea_mm2: 1.28; Cap_F: 3.3nF; AEC Category: Q200
C36 C50 C63 = C0603X103K5RACTU: as C17 on sheet Voltage Sensing-Pg4
C37 C41 C45 C46 C54 C58 C59 C67 C71 C72 = CMP-0006979-5: CAP, CERM, 0.1 uF, 25 V, +/- 10%, X7R, 0603; Manufacturer: Kemet; Polarized: N; Value: 0.1uF; U/M: EA; Cap_F: 100nF; Value1: Unknown; VDC_V: 25V; TaMin_C: -55°C; TaMax_C: 125°C; SizeArea_mm2: 1.28; SizeAreaWB_mm2: 4.68; SizeX_mm: 1.6; SizeY_mm: 0.8; SizeZ_mm: 1; AEC Category: Q200
C38 C51 C64 = CMP-0007197-4: CAP, CERM, 220 pF, 50 V, +/- 5%, C0G/NP0, 0603; Manufacturer: MuRata; TaMin_C: -55°C; Polarized: N; SizeAreaWB_mm2: 4.68; Value1: Unknown; U/M: EA; Value: 220pF; TaMax_C: 125°C; SizeZ_mm: 1; SizeX_mm: 1.6; SizeY_mm: 0.8; Value2: 50V; SizeArea_mm2: 1.28; AEC Category: Q200
C39 C42 C52 C55 C65 C68 = CMP-0006784-4: CAP, CERM, 330 pF, 50 V, +/- 5%, C0G/NP0, 0603; Manufacturer: AVX; TaMin_C: -55°C; ESR_ohm: 0.071; Polarized: N; SizeAreaWB_mm2: 4.68; Value1: 0.071 ohm; U/M: EA; Value: 330pF; TaMax_C: 125°C; SizeZ_mm: 1; SizeX_mm: 1.6; SizeY_mm: 0.8; Value2: 50V; SizeArea_mm2: 1.28; AEC Category: Q200
C40 C44 C53 C57 C66 C70 = CMP-0079720-1: CAP, CERM, 1 µF, 25 V,+/- 10%, X7R, 0603; Manufacturer: MuRata; TaMin_C: -55°C; Polarized: N; SizeAreaWB_mm2: 4.68; U/M: EA; Value: 1uF; TaMax_C: 125°C; SizeZ_mm: 1; SizeX_mm: 1.6; SizeY_mm: 0.8; Value2: 25V; SizeArea_mm2: 1.28; AEC Category: Q200
C43 C47 C48 C56 C60 C61 C69 C75 C76 = CMP-0007431-4: CAP, CERM, 1000 pF, 50 V, +/- 5%, X7R, 0603; Manufacturer: MuRata; TaMin_C: -55°C; Polarized: N; SizeAreaWB_mm2: 4.68; Value1: Unknown; U/M: EA; Value: 1000pF; TaMax_C: 125°C; SizeZ_mm: 1; SizeX_mm: 1.6; SizeY_mm: 0.8; Value2: 50V; SizeArea_mm2: 1.28; AEC Category: Q200
L10-L13 = CMP-0003155-2: as L7 on sheet Voltage Sensing-Pg4
R105 R106 R109 R110 = CMP-0081973-1: RES, 0, 0%, 0.25 W, AEC-Q200 Grade 0, 0603; Manufacturer: Vishay-Dale; SizeAreaWB_mm2: 4.68; SizeArea_mm2: 1.28; AEC Qualified: Y; AEC Category: Q200; Value: 0; SizeZ_mm: 1; SizeY_mm: 0.8; Power_W: 250mW; Value2: 0.25W; SizeX_mm: 1.6
R112 R120 R121 R129 R130 R139 = PHT0603Y1002BGT200: RES, 10.0 k, 0.1%, 0.0375 W, 0603; Manufacturer: Vishay Sfernice; CompType: Resistor; Value: 10.0k; Res_ohm: 10000; Value_Code: 10k0; Tolerance_%: 0.1; Power_W: 0.0375; VDC_V: 75; TempCo: 15 ppm/C; SizeArea_mm2: 1.28; SizeX_mm: 1.6; SizeY_mm: 0.8; SizeZ_mm: 1; EIA_Code: E192; U/M: EA; AEC Category: Q200
R113 R117 R122 R126 R131 R135 = CMP-0023143-5: RES, 49.9, 1%, 0.1 W, 0603; Manufacturer: Yageo; Power_W: 100mW; TempCo: 100 ppm/C; Value_Code: 49R9; Value: 49.9; EIA_Code: E96; SizeX_mm: 1.6; SizeY_mm: 0.8; SizeZ_mm: 1; Value2: 0.1W; SizeArea_mm2: 1.28; AEC Qualified: N; VDC_V: 75V; AEC Category: Q200; SizeAreaWB_mm2: 4.68
R114 R118 R123 R127 R132 R136 = CMP-0023780-3: RES, 15.0 k, 0.1%, 0.1 W, 0603; Manufacturer: Yageo America; Power_W: 100mW; TempCo: 25 ppm/C; Value_Code: 15k0; U/M: EA; Value: 15.0k; EIA_Code: E192; Res_ohm: 15k; SizeX_mm: 1.6; SizeY_mm: 0.8; SizeZ_mm: 1; Value2: 0.1W; SizeArea_mm2: 1.28; VDC_V: 75V; AEC Category: Q200
R115 R119 R124 R128 R133 R137 = CMP-0022003-4: RES, 10.0, 1%, 0.1 W, AEC-Q200 Grade 0, 0603; Manufacturer: Vishay-Dale; Power_W: 100mW; TempCo: 100 ppm/C; Value_Code: 10R0; Value: 10.0; EIA_Code: E96; Res_ohm: 10; SizeX_mm: 1.6; SizeY_mm: 0.8; SizeZ_mm: 1; Value2: 0.1W; SizeArea_mm2: 1.28; AEC Qualified: Y; VDC_V: 75V; AEC Category: Q200; AEC Grade: 0
R116 R125 R134 = CMP-0082532-1: RES, 499, 1%, 0.1 W, 0603; Manufacturer: Vishay-Dale; Power_W: 100mW; TempCo: 100 ppm/C; SizeAreaWB_mm2: 4.68; Value_Code: 499R; Value: 499; EIA_Code: E96; SizeX_mm: 1.6; SizeY_mm: 0.8; SizeZ_mm: 1; Value2: 0.1W; SizeArea_mm2: 1.28; AEC Qualified: N; VDC_V: 75V; AEC Category: Q200
TP26-TP28 = 5015: as TP16 on sheet Voltage Sensing-Pg4
U4 U6 U7 = CMP-0750211-1: AMC3301 Precision, ±250-mV Input, Reinforced Isolated Amplifier with Integraded DC/DC Converter, DWE0016A (SO-MOD-16); Alternate Manufacturer: Texas Instruments; SizeArea_mm2: 106.09; SizeY_mm: 10.3; SizeAreaWB_mm2: 151.29; AEC Category: Q200; AEC Qualified: N; CompType: IC; SizeZ_mm: 2.65
U5 = CMP-0041164-1: Precision, Low Noise, Low Quiescent Current Operational Amplifier, 2 to 5.5 V, -40 to 125 degC, 14-pin SOP (PW14), Green (RoHS & no Sb/Br); Manufacturer: Texas Instruments; Vio (25C)(Max)(mV): 0.025; CMRR(Min)(dB): 76; Sub Family: Low Input Bias Current Amp (<=10pA), Low Noise Amp (<=10nV/rtHz), Low Offset Voltage Amplifier (<=500uV), Low Supply Voltage Amplifier (<=2.7V), Precision Amplifier; Total Supply Voltage(Max)(+5V is 5, +/-5V is 10): 5.5; Total Supply Voltage(Min)(+5V is 5, +/-5V is 10): 2; IIB(Max)(pA): 10; Offset Drift(Typ)(uV/C): 0.32; Vn at 1kHz(Typ)(nV/rtHz): 7.5; Iq per channel(Max)(mA): 0.95; Number of Channels: 4

## Sheet Controller Card-Pg6.SchDoc
size 431 x 279 mm; Date: Not shown in title block; ApprovedBy: Not shown in title block; CheckedBy: Not shown in title block; Author: Not shown in title block; CompanyName: Not shown in title block; DrawnBy: Avinash; Engineer: Not shown in title block; Organization: Not shown in title block; Address1: Not shown in title block; Address2: Not shown in title block; Address3: Not shown in title block; Address4: Not shown in title block; DocumentNumber: 1; Revision: Use project parameter SCH_Rev; SheetNumber: 6; SheetTotal: 7; PageSetup: Record=PageOptions¦CenterHorizontal=True¦CenterVertical=True¦PrintScale=1.00¦XCorrection=1.00¦YCorrection=1.00¦PrintKind=0¦BorderSize=5000000¦LeftOffset=0¦BottomOffset=0¦Orientation=2¦PaperLength=1000¦PaperWidth=1000¦Scale=100¦PaperSource=15¦PrintQuality=600¦MediaType=1¦DitherType=10¦PrintScaleMode=1¦PaperKind=Letter
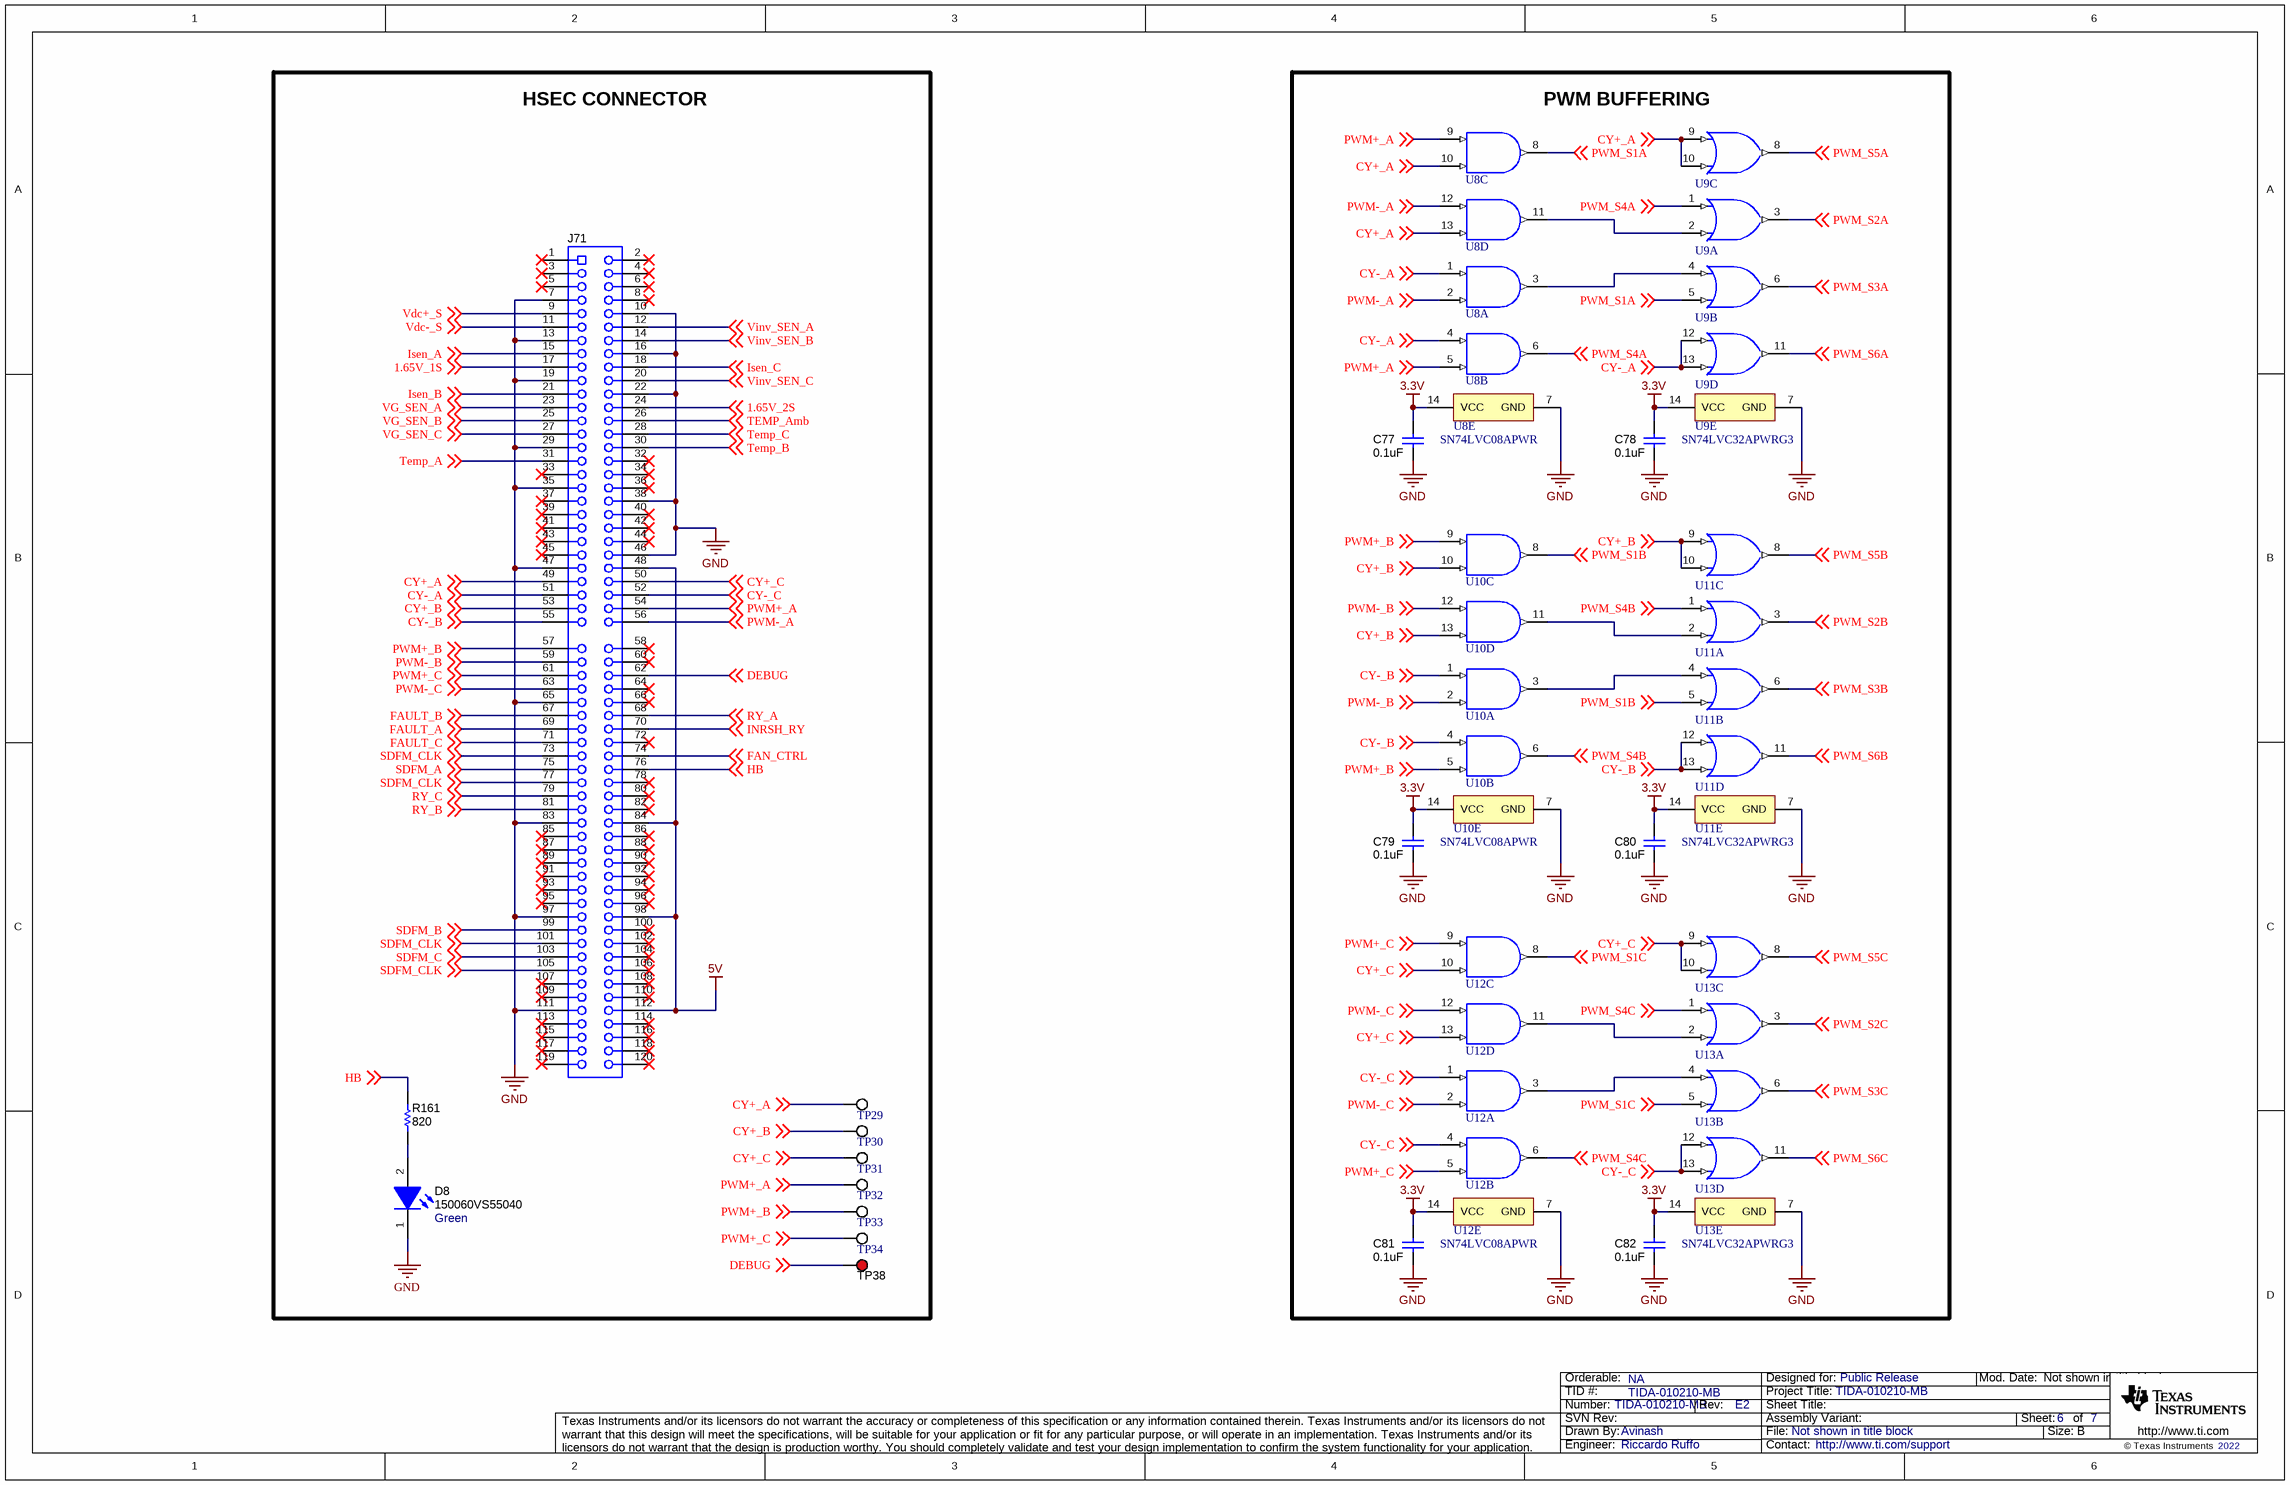
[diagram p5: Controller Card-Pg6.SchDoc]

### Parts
C77  ValueDisplayed: 0.1uF  [0603]  (hidden comment: C0603X104K3RACTU)
C78  ValueDisplayed: 0.1uF  [0603]  (hidden comment: C0603X104K3RACTU)
C79  ValueDisplayed: 0.1uF  [0603]  (hidden comment: C0603X104K3RACTU)
C80  ValueDisplayed: 0.1uF  [0603]  (hidden comment: C0603X104K3RACTU)
C81  ValueDisplayed: 0.1uF  [0603]  (hidden comment: C0603X104K3RACTU)
C82  ValueDisplayed: 0.1uF  [0603]  (hidden comment: C0603X104K3RACTU)
D8  150060VS55040  value Green  [WL-SMCD-0603]
J71  HSEC8-160-01-L-DV-A-BL  [controlCARD-120HSEC]  (value not drawn)
R161  ValueDisplayed: 820  [0603]  (hidden comment: RC0603FR-07820RL)
TP29  5015  [Testpoint_Keystone_Miniature]  (value not drawn)
TP30  5015  [Testpoint_Keystone_Miniature]  (value not drawn)
TP31  5015  [Testpoint_Keystone_Miniature]  (value not drawn)
TP32  5015  [Testpoint_Keystone_Miniature]  (value not drawn)
TP33  5015  [Testpoint_Keystone_Miniature]  (value not drawn)
TP34  5015  [Testpoint_Keystone_Miniature]  (value not drawn)
TP38  5000  [Keystone5000]  (value not drawn)
U8  SN74LVC08APWR  [PW0014A_N]  (value not drawn)  (parts A,B,C,D,E of 5)
U9  SN74LVC32APWRG3  [PW0014A_N]  (value not drawn)  (parts A,B,C,D,E of 5)
U10  SN74LVC08APWR  [PW0014A_N]  (value not drawn)  (parts A,B,C,D,E of 5)
U11  SN74LVC32APWRG3  [PW0014A_N]  (value not drawn)  (parts A,B,C,D,E of 5)
U12  SN74LVC08APWR  [PW0014A_N]  (value not drawn)  (parts A,B,C,D,E of 5)
U13  SN74LVC32APWRG3  [PW0014A_N]  (value not drawn)  (parts A,B,C,D,E of 5)

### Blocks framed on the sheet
HSEC CONNECTOR: D8 J71 R161 TP29-TP34 TP38
PWM BUFFERING: C77-C82 U8-U13

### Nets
3.3V: C77.2 C78.2 C79.2 C80.2 C81.2 C82.2 U8.14(VCC) U9.14(VCC) U10.14(VCC) U11.14(VCC) U12.14(VCC) U13.14(VCC)
5V: J71.48 J71.84 J71.98 J71.112
GND: C77.1 C78.1 C79.1 C80.1 C81.1 C82.1 D8.1(K) J71.7 J71.10 J71.13 J71.16 J71.19 J71.22 J71.29 J71.35 J71.38 J71.46 J71.47 J71.65 J71.83 J71.97 J71.111 U8.7(GND) U9.7(GND) U10.7(GND) U11.7(GND) U12.7(GND) U13.7(GND)
1.65V_1S: J71.17 ; off-sheet 1.65V_1S
1.65V_2S: J71.24 ; off-sheet 1.65V_2S
CY+_A: J71.49 TP29.1 U8.10(3B) U8.13(4B) U9.9(3A) U9.10(3B) ; off-sheet CY+_A
CY+_B: J71.53 TP30.1 U10.10(3B) U10.13(4B) U11.9(3A) U11.10(3B) ; off-sheet CY+_B
CY+_C: J71.50 TP31.1 U12.10(3B) U12.13(4B) U13.9(3A) U13.10(3B) ; off-sheet CY+_C
CY-_A: J71.51 U8.1(1A) U8.4(2A) U9.12(4A) U9.13(4B) ; off-sheet CY-_A
CY-_B: J71.55 U10.1(1A) U10.4(2A) U11.12(4A) U11.13(4B) ; off-sheet CY-_B
CY-_C: J71.52 U12.1(1A) U12.4(2A) U13.12(4A) U13.13(4B) ; off-sheet CY-_C
DEBUG: J71.62 TP38.1 ; off-sheet DEBUG
FAN_CTRL: J71.74 ; off-sheet FAN_CTRL
FAULT_A: J71.69 ; off-sheet FAULT_A
FAULT_B: J71.67 ; off-sheet FAULT_B
FAULT_C: J71.71 ; off-sheet FAULT_C
HB: J71.76 R161.1 ; off-sheet HB
INRSH_RY: J71.70 ; off-sheet INRSH_RY
Isen_A: J71.15 ; off-sheet Isen_A
Isen_B: J71.21 ; off-sheet Isen_B
Isen_C: J71.18 ; off-sheet Isen_C
PWM+_A: J71.54 TP32.1 U8.5(2B) U8.9(3A) ; off-sheet PWM+_A
PWM+_B: J71.57 TP33.1 U10.5(2B) U10.9(3A) ; off-sheet PWM+_B
PWM+_C: J71.61 TP34.1 U12.5(2B) U12.9(3A) ; off-sheet PWM+_C
PWM-_A: J71.56 U8.2(1B) U8.12(4A) ; off-sheet PWM-_A
PWM-_B: J71.59 U10.2(1B) U10.12(4A) ; off-sheet PWM-_B
PWM-_C: J71.63 U12.2(1B) U12.12(4A) ; off-sheet PWM-_C
PWM_S1A: U8.8(3Y) U9.5(2B) ; off-sheet PWM_S1A
PWM_S1B: U10.8(3Y) U11.5(2B) ; off-sheet PWM_S1B
PWM_S1C: U12.8(3Y) U13.5(2B) ; off-sheet PWM_S1C
PWM_S2A: U9.3(1Y) ; off-sheet PWM_S2A
PWM_S2B: U11.3(1Y) ; off-sheet PWM_S2B
PWM_S2C: U13.3(1Y) ; off-sheet PWM_S2C
PWM_S3A: U9.6(2Y) ; off-sheet PWM_S3A
PWM_S3B: U11.6(2Y) ; off-sheet PWM_S3B
PWM_S3C: U13.6(2Y) ; off-sheet PWM_S3C
PWM_S4A: U8.6(2Y) U9.1(1A) ; off-sheet PWM_S4A
PWM_S4B: U10.6(2Y) U11.1(1A) ; off-sheet PWM_S4B
PWM_S4C: U12.6(2Y) U13.1(1A) ; off-sheet PWM_S4C
PWM_S5A: U9.8(3Y) ; off-sheet PWM_S5A
PWM_S5B: U11.8(3Y) ; off-sheet PWM_S5B
PWM_S5C: U13.8(3Y) ; off-sheet PWM_S5C
PWM_S6A: U9.11(4Y) ; off-sheet PWM_S6A
PWM_S6B: U11.11(4Y) ; off-sheet PWM_S6B
PWM_S6C: U13.11(4Y) ; off-sheet PWM_S6C
RY_A: J71.68 ; off-sheet RY_A
RY_B: J71.81 ; off-sheet RY_B
RY_C: J71.79 ; off-sheet RY_C
SDFM_A: J71.75 ; off-sheet SDFM_A
SDFM_B: J71.99 ; off-sheet SDFM_B
SDFM_C: J71.103 ; off-sheet SDFM_C
SDFM_CLK: J71.73 J71.77 J71.101 J71.105 ; off-sheet SDFM_CLK
Temp_A: J71.31 ; off-sheet Temp_A
TEMP_Amb: J71.26 ; off-sheet TEMP_Amb
Temp_B: J71.30 ; off-sheet Temp_B
Temp_C: J71.28 ; off-sheet Temp_C
Vdc+_S: J71.9 ; off-sheet Vdc+_S
Vdc-_S: J71.11 ; off-sheet Vdc-_S
VG_SEN_A: J71.23 ; off-sheet VG_SEN_A
VG_SEN_B: J71.25 ; off-sheet VG_SEN_B
VG_SEN_C: J71.27 ; off-sheet VG_SEN_C
Vinv_SEN_A: J71.12 ; off-sheet Vinv_SEN_A
Vinv_SEN_B: J71.14 ; off-sheet Vinv_SEN_B
Vinv_SEN_C: J71.20 ; off-sheet Vinv_SEN_C
NetD8_2: D8.2(A) R161.2
NetU8_3: U8.3(1Y) U9.4(2A)
NetU8_11: U8.11(4Y) U9.2(1B)
NetU10_3: U10.3(1Y) U11.4(2A)
NetU10_11: U10.11(4Y) U11.2(1B)
NetU12_3: U12.3(1Y) U13.4(2A)
NetU12_11: U12.11(4Y) U13.2(1B)

Not connected (* = marked no-connect by the designer): J71 1* 2* 3* 4* 5* 6* 8* 32* 33* 34* 36* 37* 39* 40* 41* 42* 43* 44* 45* 58* 60* 64* 66* 72* 78* 80* 82* 85* 86* 87* 88* 89* 90* 91* 92* 93* 94* 95* 96* 100* 102* 104* 106* 107* 108* 109* 110* 113* 114* 115* 116* 117* 118* 119* 120*

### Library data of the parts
C77-C82 = CMP-0006979-5: CAP, CERM, 0.1 uF, 25 V, +/- 10%, X7R, 0603; Manufacturer: Kemet; Polarized: N; Value: 0.1uF; U/M: EA; Cap_F: 100nF; Value1: Unknown; VDC_V: 25V; TaMin_C: -55°C; TaMax_C: 125°C; AEC Category: Q200; SizeArea_mm2: 1.28; SizeAreaWB_mm2: 4.68; SizeX_mm: 1.6; SizeY_mm: 0.8; SizeZ_mm: 1
D8 = CMP-0081648-2: LED, Green, SMD; Manufacturer: Wurth Elektronik; Io_A: 20mA; Power_TotalModule: 48mW; Vr_V: 5V; SizeAreaWB_mm2: 4.68; Tjmax_C: 115°C; Value1: 0.048W; Angle: 140; SizeZ_mm: 0.5; SizeX_mm: 1.6; SizeY_mm: 0.8; Ir_A: 10µA; Vf_V: 2V; SizeArea_mm2: 1.28; Type: AlInGaP
J71 = CMP-0003814-2: C2000 controlCARD-120HSEC connector, SMT; Manufacturer: Samtec; Note: The pin numbering does not match Samtec datasheet
R161 = CMP-0023288-5: RES, 820, 1%, 0.1 W, 0603; Manufacturer: Yageo; Value: 820; Value_Code: 820R; Power_W: 100mW; Value2: 0.1W; VDC_V: 75V; TempCo: 100 ppm/C; SizeArea_mm2: 1.28; SizeX_mm: 1.6; SizeY_mm: 0.8; SizeZ_mm: 1; AEC Category: Q200; AEC Qualified: N; SizeAreaWB_mm2: 4.68
TP29-TP34 = 5015: as TP16 on sheet Voltage Sensing-Pg4
TP38 = CMP-0055137-1: Test Point, Miniature, Red, TH; Manufacturer: Keystone; CNHeader: FALSE; ContactFinish: Silver; CT: TRUE; Green_Lifecycle: Active; Green_REACh: Passed
U8 U10 U12 = CMP-0054477-1: Quadruple 2-Input Positive-AND Gate, PW0014A, LARGE T&R; Manufacturer: Texas Instruments; Schmitt Trigger: No; Output Drive (IOL/IOH)(Max)(mA): -24/24; Rating: Catalog; ICC @ Nom Voltage(Max)(mA): 0.01; Technology Family: LVC; Voltage(Nom)(V): 1.8,2.5,2.7,3.3; Input Type: TTL; Bits(#): 4; VCC(Max)(V): 3.6; F @ Nom Voltage(Max)(Mhz): 70; VCC(Min)(V): 1.65; tpd @ Nom Voltage(Max)(ns): 9.8,6.9,4.8,4.1
U9 U11 U13 = CMP-0050882-1: Quadruple 2-Input Positive-OR Gate, PW0014A, LARGE T&R; Manufacturer: Texas Instruments; VCC(Min)(V): 1.65; Bits(#): 4; Output Drive (IOL/IOH)(Max)(mA): 24/-24; Output Type: TTL; Rating: Catalog; F @ Nom Voltage(Max)(Mhz): 70; tpd @ Nom Voltage(Max)(ns): 8.7,5.4,4.4,3.8; ICC @ Nom Voltage(Max)(mA): 0.04; Voltage(Nom)(V): 1.8,2.5,2.7,3.3; VCC(Max)(V): 3.6

## Sheet Hardware-Pg7.SchDoc
size 431 x 279 mm; Date: Not shown in title block; ApprovedBy: Not shown in title block; CheckedBy: Not shown in title block; Author: Not shown in title block; CompanyName: Not shown in title block; DrawnBy: Avinash; Engineer: Not shown in title block; Organization: Not shown in title block; Address1: Not shown in title block; Address2: Not shown in title block; Address3: Not shown in title block; Address4: Not shown in title block; DocumentNumber: 1; Revision: Use project parameter SCH_Rev; SheetNumber: 7; SheetTotal: 7; PageSetup: Record=PageOptions¦CenterHorizontal=True¦CenterVertical=True¦PrintScale=1.00¦XCorrection=1.00¦YCorrection=1.00¦PrintKind=0¦BorderSize=5000000¦LeftOffset=0¦BottomOffset=0¦Orientation=2¦PaperLength=1000¦PaperWidth=1000¦Scale=100¦PaperSource=15¦PrintQuality=600¦MediaType=1¦DitherType=10¦PaperKind=Letter¦PrintScaleMode=1
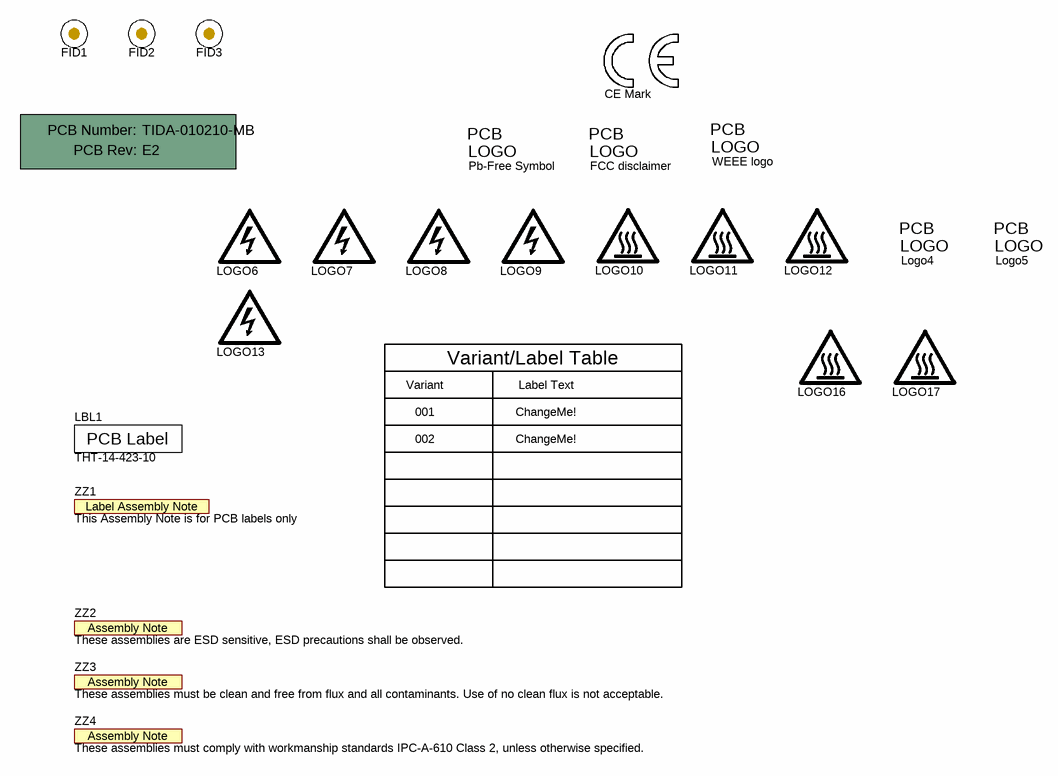
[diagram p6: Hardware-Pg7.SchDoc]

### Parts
!PCB1  Printed Circuit Board  (value not drawn)  (mechanical)
FID1  Fiducial  [Fiducial10-30]  (value not drawn)
FID2  Fiducial  [Fiducial10-30]  (value not drawn)
FID3  Fiducial  [Fiducial10-30]  (value not drawn)
LBL1  THT-14-423-10  [Label_650x200]
Logo1  WEEE logo  [WEEE_Minimum]  (no BOM)
Logo2  Pb-Free Symbol  [Pb-Free_Overlay_Medium]  (no BOM)
Logo3  FCC disclaimer  [FCC_disclaimer]  (no BOM)
Logo4  CAUTION.  READ USER GUIDE BEFORE USE  [IEC_Caution_Medium]  (value not drawn)  (no BOM)
Logo5  ESD Susceptible  [ESD_Overlay_Medium]  (value not drawn)  (no BOM)
LOGO6  DANGER HIGH VOLTAGE  [IEC_HighVoltage_Medium]  (value not drawn)  (no BOM)
LOGO7  DANGER HIGH VOLTAGE  [IEC_HighVoltage_Medium]  (value not drawn)  (no BOM)
LOGO8  DANGER HIGH VOLTAGE  [IEC_HighVoltage_Medium]  (value not drawn)  (no BOM)
LOGO9  DANGER HIGH VOLTAGE  [IEC_HighVoltage_Medium]  (value not drawn)  (no BOM)
LOGO10  CAUTION HOT SURFACE  [IEC_HotSurface_Medium]  (value not drawn)  (no BOM)
LOGO11  CAUTION HOT SURFACE  [IEC_HotSurface_Medium]  (value not drawn)  (no BOM)
LOGO12  CAUTION HOT SURFACE  [IEC_HotSurface_Medium]  (value not drawn)  (no BOM)
LOGO13  DANGER HIGH VOLTAGE  [IEC_HighVoltage_Medium]  (value not drawn)  (no BOM)
Logo15  CE Mark  [CE_Mark_5mm]  (no BOM)
LOGO16  CAUTION HOT SURFACE  [IEC_HotSurface_Medium]  (value not drawn)  (no BOM)
LOGO17  CAUTION HOT SURFACE  [IEC_HotSurface_Medium]  (value not drawn)  (no BOM)
ZZ1  This Assembly Note is for PCB labels only  [AssemblyNoteLabel]  (no BOM)
ZZ2  These assemblies are ESD sensitive, ESD precautions shall be observed.  [AssemblyNote]  (no BOM)
ZZ3  These assemblies must be clean and free from flux and all contaminants. Use of no clean flux is not acceptable.  [AssemblyNote]  (no BOM)
ZZ4  These assemblies must comply with workmanship standards IPC-A-610 Class 2, unless otherwise specified.  [AssemblyNote]  (no BOM)

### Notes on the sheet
- Variant
- Variant/Label Table
- Label Text
- 001
- 002
- ChangeMe!

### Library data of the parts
!PCB1 = CMP-0003618-2: Manufacturer: Any; PartNumber: TIDA-010210-MB
FID1-FID3 = CMP-0077181-1: Fiducial mark.  There is nothing to buy or mount.
LBL1 = CMP-0003625-1: Thermal Transfer Printable Labels, 0.650" W x 0.200" H - 10,000 per roll; Manufacturer: Brady; Note: Size: 0.65" x 0.20 "
Logo1 = CMP-0074769-1
Logo2 = CMP-0074839-1: SymbolCreator: a0412235
Logo3 = CMP-0074847-1: FCC_disclaimer
Logo4 = CMP-0074836-1: IEC 61010-1 Caution Warning; SymbolCreator: a0412235; Lib Reference: IEC_Caution; Library Reference: Logo
Logo5 = CMP-0074840-1: ESD Susceptible Symbol; SymbolCreator: a0412235; Lib Reference: ESD_Susceptible; Library Reference: Logo
LOGO6-LOGO9 LOGO13 = CMP-0074835-1: IEC 61010-1 High Voltage Warning; SymbolCreator: a0412235; Lib Reference: IEC_HighVoltage
LOGO10-LOGO12 LOGO16 LOGO17 = CMP-0074837-1: IEC 61010-1 Hot Surface Warning; SymbolCreator: a0412235; Lib Reference: IEC_HotSurface
Logo15 = CMP-0074844-1: SymbolCreator: a0412235
ZZ1 = CMP-0003616-3
ZZ2 = CMP-0077236-1
ZZ3 = CMP-0077237-1
ZZ4 = CMP-0077238-1

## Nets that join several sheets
1.65V_1: Voltage Sensing-Pg4 (8 pins), Current Sensing-Pg5 (U5.12)
3.3V: Power Supply and Protection-Pg3 (14 pins), Voltage Sensing-Pg4 (L7.1 L8.1 L9.1), Current Sensing-Pg5 (L10.1 L11.2 L12.2 L13.2), Controller Card-Pg6 (12 pins)
5V: Power Stage-Pg2 (9 pins), Power Supply and Protection-Pg3 (14 pins), Controller Card-Pg6 (J71.48 J71.84 J71.98 J71.112)
+12V: Power Stage-Pg2 (15 pins), Power Supply and Protection-Pg3 (9 pins)
GND: Power Stage-Pg2 (25 pins), Power Supply and Protection-Pg3 (47 pins), Voltage Sensing-Pg4 (21 pins), Current Sensing-Pg5 (26 pins), Controller Card-Pg6 (28 pins)
PGND: Power Stage-Pg2 (39 pins), Voltage Sensing-Pg4 (8 pins)
1.65V_1S: Voltage Sensing-Pg4 (C74.1 R140.2), Controller Card-Pg6 (J71.17)
1.65V_2S: Voltage Sensing-Pg4 (C31.1 R108.2), Controller Card-Pg6 (J71.24)
DC+: Power Stage-Pg2 (13 pins), Power Supply and Protection-Pg3 (J76.1 J76.2), Voltage Sensing-Pg4 (R54.1)
DC-: Power Stage-Pg2 (13 pins), Power Supply and Protection-Pg3 (J77.1 J77.2), Voltage Sensing-Pg4 (R69.1)
FAN_CTRL: Power Supply and Protection-Pg3 (R149.1 R153.1 R158.1), Controller Card-Pg6 (J71.74)
FAULT_A: Power Supply and Protection-Pg3 (C95.1 R147.2 R150.2), Controller Card-Pg6 (J71.69)
FAULT_A+: Power Stage-Pg2 (J2.3), Power Supply and Protection-Pg3 (U19.1)
FAULT_A-: Power Stage-Pg2 (J37.3), Power Supply and Protection-Pg3 (U19.2)
FAULT_B: Power Supply and Protection-Pg3 (C99.1 R152.2 R154.2), Controller Card-Pg6 (J71.67)
FAULT_B+: Power Stage-Pg2 (J5.3), Power Supply and Protection-Pg3 (U20.1)
FAULT_B-: Power Stage-Pg2 (J39.3), Power Supply and Protection-Pg3 (U20.2)
FAULT_C: Power Supply and Protection-Pg3 (C103.1 R157.2 R159.2), Controller Card-Pg6 (J71.71)
FAULT_C+: Power Stage-Pg2 (J4.3), Power Supply and Protection-Pg3 (U22.1)
FAULT_C-: Power Stage-Pg2 (J38.3), Power Supply and Protection-Pg3 (U22.2)
Iind_A: Power Stage-Pg2 (R3.3), Current Sensing-Pg5 (R119.1)
Iind_A_Rtn: Power Stage-Pg2 (R3.4), Current Sensing-Pg5 (R115.1)
Iind_B: Power Stage-Pg2 (R6.3), Current Sensing-Pg5 (R128.1)
Iind_B_Rtn: Power Stage-Pg2 (R6.4), Current Sensing-Pg5 (R124.1)
Iind_C: Power Stage-Pg2 (R9.3), Current Sensing-Pg5 (R137.1)
Iind_C_Rtn: Power Stage-Pg2 (R9.4), Current Sensing-Pg5 (R133.1)
INRSH_RY: Power Stage-Pg2 (R21.1 R22.1 R23.1), Controller Card-Pg6 (J71.70)
Isen_A: Current Sensing-Pg5 (C38.1 R116.2), Controller Card-Pg6 (J71.15)
Isen_B: Current Sensing-Pg5 (C51.1 R125.2), Controller Card-Pg6 (J71.21)
Isen_C: Current Sensing-Pg5 (C64.1 R134.2), Controller Card-Pg6 (J71.18)
Ph_A: Power Stage-Pg2 (J67.1 K2.3 TP10.1), Voltage Sensing-Pg4 (R51.1)
Ph_B: Power Stage-Pg2 (J68.1 K4.3 TP11.1), Voltage Sensing-Pg4 (R78.1)
Ph_C: Power Stage-Pg2 (J69.1 K6.3 TP12.1), Voltage Sensing-Pg4 (R100.1)
PWM_S1A: Power Stage-Pg2 (J2.1), Controller Card-Pg6 (U8.8 U9.5)
PWM_S1B: Power Stage-Pg2 (J5.1), Controller Card-Pg6 (U10.8 U11.5)
PWM_S1C: Power Stage-Pg2 (J4.1), Controller Card-Pg6 (U12.8 U13.5)
PWM_S2A: Power Stage-Pg2 (J2.2), Controller Card-Pg6 (U9.3)
PWM_S2B: Power Stage-Pg2 (J5.2), Controller Card-Pg6 (U11.3)
PWM_S2C: Power Stage-Pg2 (J4.2), Controller Card-Pg6 (U13.3)
PWM_S3A: Power Stage-Pg2 (J37.1), Controller Card-Pg6 (U9.6)
PWM_S3B: Power Stage-Pg2 (J39.1), Controller Card-Pg6 (U11.6)
PWM_S3C: Power Stage-Pg2 (J38.1), Controller Card-Pg6 (U13.6)
PWM_S4A: Power Stage-Pg2 (J37.2), Controller Card-Pg6 (U8.6 U9.1)
PWM_S4B: Power Stage-Pg2 (J39.2), Controller Card-Pg6 (U10.6 U11.1)
PWM_S4C: Power Stage-Pg2 (J38.2), Controller Card-Pg6 (U12.6 U13.1)
PWM_S5A: Power Stage-Pg2 (J3.1), Controller Card-Pg6 (U9.8)
PWM_S5B: Power Stage-Pg2 (J14.1), Controller Card-Pg6 (U11.8)
PWM_S5C: Power Stage-Pg2 (J34.1), Controller Card-Pg6 (U13.8)
PWM_S6A: Power Stage-Pg2 (J3.2), Controller Card-Pg6 (U9.11)
PWM_S6B: Power Stage-Pg2 (J14.2), Controller Card-Pg6 (U11.11)
PWM_S6C: Power Stage-Pg2 (J34.2), Controller Card-Pg6 (U13.11)
RY_A: Power Stage-Pg2 (R24.1), Controller Card-Pg6 (J71.68)
RY_B: Power Stage-Pg2 (R25.1), Controller Card-Pg6 (J71.81)
RY_C: Power Stage-Pg2 (R26.1), Controller Card-Pg6 (J71.79)
SDFM_A: Current Sensing-Pg5 (R105.2), Controller Card-Pg6 (J71.75)
SDFM_B: Current Sensing-Pg5 (R106.2), Controller Card-Pg6 (J71.99)
SDFM_C: Current Sensing-Pg5 (R109.2), Controller Card-Pg6 (J71.103)
SDFM_CLK: Current Sensing-Pg5 (R110.2), Controller Card-Pg6 (J71.73 J71.77 J71.101 J71.105)
Temp_A: Power Supply and Protection-Pg3 (C98.2 R148.2), Controller Card-Pg6 (J71.31)
TEMP_Amb: Power Supply and Protection-Pg3 (C101.2 R156.2), Controller Card-Pg6 (J71.26)
Temp_B: Power Supply and Protection-Pg3 (C94.2 R146.2), Controller Card-Pg6 (J71.30)
Temp_C: Power Supply and Protection-Pg3 (C85.2 R142.2), Controller Card-Pg6 (J71.28)
Vdc+_S: Voltage Sensing-Pg4 (C19.1 R47.2), Controller Card-Pg6 (J71.9)
Vdc-_S: Voltage Sensing-Pg4 (C25.1 R74.2), Controller Card-Pg6 (J71.11)
VG_SEN_A: Voltage Sensing-Pg4 (C18.1 R46.2), Controller Card-Pg6 (J71.23)
VG_SEN_B: Voltage Sensing-Pg4 (C24.1 R73.2), Controller Card-Pg6 (J71.25)
VG_SEN_C: Voltage Sensing-Pg4 (C29.1 R96.2), Controller Card-Pg6 (J71.27)
Vinv_SEN_A: Voltage Sensing-Pg4 (C17.1 R45.2), Controller Card-Pg6 (J71.12)
Vinv_SEN_B: Voltage Sensing-Pg4 (C23.1 R72.2), Controller Card-Pg6 (J71.14)
Vinv_SEN_C: Voltage Sensing-Pg4 (C28.1 R95.2), Controller Card-Pg6 (J71.20)
Vsen_A: Power Stage-Pg2 (5 pins), Voltage Sensing-Pg4 (R48.1), Current Sensing-Pg5 (7 pins)
Vsen_B: Power Stage-Pg2 (5 pins), Voltage Sensing-Pg4 (R75.1), Current Sensing-Pg5 (7 pins)
Vsen_C: Power Stage-Pg2 (5 pins), Voltage Sensing-Pg4 (R97.1), Current Sensing-Pg5 (7 pins)

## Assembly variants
001: not fitted FID1 FID2 FID3 J72 J79 J80 J81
